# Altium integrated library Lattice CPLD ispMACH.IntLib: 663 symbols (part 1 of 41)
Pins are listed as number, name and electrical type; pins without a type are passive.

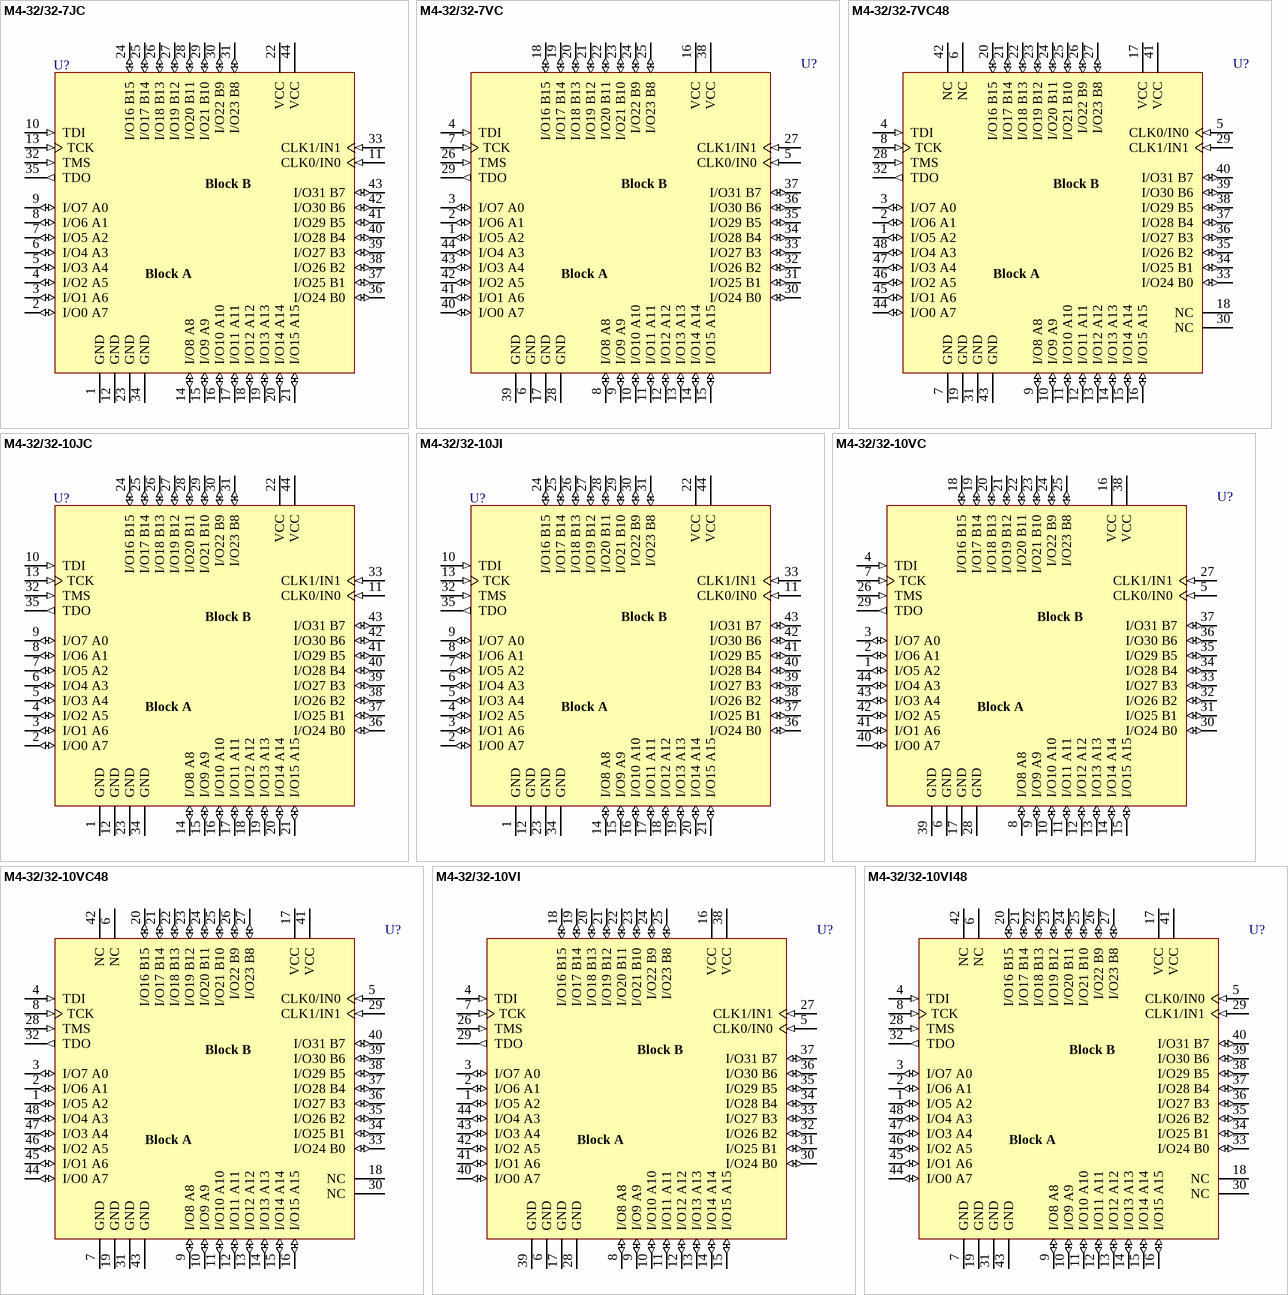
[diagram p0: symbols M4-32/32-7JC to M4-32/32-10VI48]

## M4-32/32-7JC
designator U?
High-Performance EE CMOS In-System Programmable Logic
footprint PLCC44_N (Leaded Chip Carrier, 44-Leads, Body 16.6x16.6mm, Pitch 1.27mm, IPC Medium Density)
footprint PLCC44_L (Leaded Chip Carrier, 44-Leads, Body 16.6x16.6mm, Pitch 1.27mm, IPC High Density)
footprint PLCC44_M (Leaded Chip Carrier, 44-Leads, Body 16.6x16.6mm, Pitch 1.27mm, IPC Low Density)
3D model M4-PLCC44 (44-Pin Leaded Chip Carrier 1.27 mm Pitch)
pins: 1 GND (power), 2 I/O0 A7 (io), 3 I/O1 A6 (io), 4 I/O2 A5 (io), 5 I/O3 A4 (io), 6 I/O4 A3 (io), 7 I/O5 A2 (io), 8 I/O6 A1 (io), 9 I/O7 A0 (io), 10 TDI (in), 11 CLK0/IN0 (in), 12 GND (power), 13 TCK (in), 14 I/O8 A8 (io), 15 I/O9 A9 (io), 16 I/O10 A10 (io), 17 I/O11 A11 (io), 18 I/O12 A12 (io), 19 I/O13 A13 (io), 20 I/O14 A14 (io), 21 I/O15 A15 (io), 22 VCC (power), 23 GND (power), 24 I/O16 B15 (io), 25 I/O17 B14 (io), 26 I/O18 B13 (io), 27 I/O19 B12 (io), 28 I/O20 B11 (io), 29 I/O21 B10 (io), 30 I/O22 B9 (io), 31 I/O23 B8 (io), 32 TMS (in), 33 CLK1/IN1 (in), 34 GND (power), 35 TDO (out), 36 I/O24 B0 (io), 37 I/O25 B1 (io), 38 I/O26 B2 (io), 39 I/O27 B3 (io), 40 I/O28 B4 (io), 41 I/O29 B5 (io), 42 I/O30 B6 (io), 43 I/O31 B7 (io), 44 VCC (power)

## M4-32/32-7VC
designator U?
High-Performance EE CMOS In-System Programmable Logic
footprint TQFP44_N (Thin QFP, 44-Leads, Body 10x10mm, Pitch 0.8mm, IPC Medium Density)
footprint TQFP44_L (Thin QFP, 44-Leads, Body 10x10mm, Pitch 0.8mm, IPC High Density)
footprint TQFP44_M (Thin QFP, 44-Leads, Body 10x10mm, Pitch 0.8mm, IPC Low Density)
3D model M4-TQFP44 (44-Pin Thin Quad Flat Pack 0.8 mm Pitch)
pins: 1 I/O5 A2 (io), 2 I/O6 A1 (io), 3 I/O7 A0 (io), 4 TDI (in), 5 CLK0/IN0 (in), 6 GND (power), 7 TCK (in), 8 I/O8 A8 (io), 9 I/O9 A9 (io), 10 I/O10 A10 (io), 11 I/O11 A11 (io), 12 I/O12 A12 (io), 13 I/O13 A13 (io), 14 I/O14 A14 (io), 15 I/O15 A15 (io), 16 VCC (power), 17 GND (power), 18 I/O16 B15 (io), 19 I/O17 B14 (io), 20 I/O18 B13 (io), 21 I/O19 B12 (io), 22 I/O20 B11 (io), 23 I/O21 B10 (io), 24 I/O22 B9 (io), 25 I/O23 B8 (io), 26 TMS (in), 27 CLK1/IN1 (in), 28 GND (power), 29 TDO (out), 30 I/O24 B0 (io), 31 I/O25 B1 (io), 32 I/O26 B2 (io), 33 I/O27 B3 (io), 34 I/O28 B4 (io), 35 I/O29 B5 (io), 36 I/O30 B6 (io), 37 I/O31 B7 (io), 38 VCC (power), 39 GND (power), 40 I/O0 A7 (io), 41 I/O1 A6 (io), 42 I/O2 A5 (io), 43 I/O3 A4 (io), 44 I/O4 A3 (io)

## M4-32/32-7VC48
designator U?
High-Performance EE CMOS In-System Programmable Logic
footprint TQFP48_N (Thin QFP, 48-Leads, Body 7x7mm, Pitch 0.5mm, IPC Medium Density)
footprint TQFP48_L (Thin QFP, 48-Leads, Body 7x7mm, Pitch 0.5mm, IPC High Density)
footprint TQFP48_M (Thin QFP, 48-Leads, Body 7x7mm, Pitch 0.5mm, IPC Low Density)
3D model M4-TQFP48 (48-Pin Thin Quad Flat Pack 0.5 mm Pitch)
pins: 1 I/O5 A2 (io), 2 I/O6 A1 (io), 3 I/O7 A0 (io), 4 TDI (in), 5 CLK0/IN0 (in), 6 NC, 7 GND (power), 8 TCK (in), 9 I/O8 A8 (io), 10 I/O9 A9 (io), 11 I/O10 A10 (io), 12 I/O11 A11 (io), 13 I/O12 A12 (io), 14 I/O13 A13 (io), 15 I/O14 A14 (io), 16 I/O15 A15 (io), 17 VCC (power), 18 NC, 19 GND (power), 20 I/O16 B15 (io), 21 I/O17 B14 (io), 22 I/O18 B13 (io), 23 I/O19 B12 (io), 24 I/O20 B11 (io), 25 I/O21 B10 (io), 26 I/O22 B9 (io), 27 I/O23 B8 (io), 28 TMS (in), 29 CLK1/IN1 (in), 30 NC, 31 GND (power), 32 TDO (out), 33 I/O24 B0 (io), 34 I/O25 B1 (io), 35 I/O26 B2 (io), 36 I/O27 B3 (io), 37 I/O28 B4 (io), 38 I/O29 B5 (io), 39 I/O30 B6 (io), 40 I/O31 B7 (io), 41 VCC (power), 42 NC, 43 GND (power), 44 I/O0 A7 (io), 45 I/O1 A6 (io), 46 I/O2 A5 (io), 47 I/O3 A4 (io), 48 I/O4 A3 (io)

## M4-32/32-10JC
designator U?
High-Performance EE CMOS In-System Programmable Logic
footprint PLCC44_N (Leaded Chip Carrier, 44-Leads, Body 16.6x16.6mm, Pitch 1.27mm, IPC Medium Density)
footprint PLCC44_L (Leaded Chip Carrier, 44-Leads, Body 16.6x16.6mm, Pitch 1.27mm, IPC High Density)
footprint PLCC44_M (Leaded Chip Carrier, 44-Leads, Body 16.6x16.6mm, Pitch 1.27mm, IPC Low Density)
3D model M4-PLCC44 (44-Pin Leaded Chip Carrier 1.27 mm Pitch)
pins: 1 GND (power), 2 I/O0 A7 (io), 3 I/O1 A6 (io), 4 I/O2 A5 (io), 5 I/O3 A4 (io), 6 I/O4 A3 (io), 7 I/O5 A2 (io), 8 I/O6 A1 (io), 9 I/O7 A0 (io), 10 TDI (in), 11 CLK0/IN0 (in), 12 GND (power), 13 TCK (in), 14 I/O8 A8 (io), 15 I/O9 A9 (io), 16 I/O10 A10 (io), 17 I/O11 A11 (io), 18 I/O12 A12 (io), 19 I/O13 A13 (io), 20 I/O14 A14 (io), 21 I/O15 A15 (io), 22 VCC (power), 23 GND (power), 24 I/O16 B15 (io), 25 I/O17 B14 (io), 26 I/O18 B13 (io), 27 I/O19 B12 (io), 28 I/O20 B11 (io), 29 I/O21 B10 (io), 30 I/O22 B9 (io), 31 I/O23 B8 (io), 32 TMS (in), 33 CLK1/IN1 (in), 34 GND (power), 35 TDO (out), 36 I/O24 B0 (io), 37 I/O25 B1 (io), 38 I/O26 B2 (io), 39 I/O27 B3 (io), 40 I/O28 B4 (io), 41 I/O29 B5 (io), 42 I/O30 B6 (io), 43 I/O31 B7 (io), 44 VCC (power)

## M4-32/32-10JI
designator U?
High-Performance EE CMOS In-System Programmable Logic
footprint PLCC44_N (Leaded Chip Carrier, 44-Leads, Body 16.6x16.6mm, Pitch 1.27mm, IPC Medium Density)
footprint PLCC44_L (Leaded Chip Carrier, 44-Leads, Body 16.6x16.6mm, Pitch 1.27mm, IPC High Density)
footprint PLCC44_M (Leaded Chip Carrier, 44-Leads, Body 16.6x16.6mm, Pitch 1.27mm, IPC Low Density)
3D model M4-PLCC44 (44-Pin Leaded Chip Carrier 1.27 mm Pitch)
pins: 1 GND (power), 2 I/O0 A7 (io), 3 I/O1 A6 (io), 4 I/O2 A5 (io), 5 I/O3 A4 (io), 6 I/O4 A3 (io), 7 I/O5 A2 (io), 8 I/O6 A1 (io), 9 I/O7 A0 (io), 10 TDI (in), 11 CLK0/IN0 (in), 12 GND (power), 13 TCK (in), 14 I/O8 A8 (io), 15 I/O9 A9 (io), 16 I/O10 A10 (io), 17 I/O11 A11 (io), 18 I/O12 A12 (io), 19 I/O13 A13 (io), 20 I/O14 A14 (io), 21 I/O15 A15 (io), 22 VCC (power), 23 GND (power), 24 I/O16 B15 (io), 25 I/O17 B14 (io), 26 I/O18 B13 (io), 27 I/O19 B12 (io), 28 I/O20 B11 (io), 29 I/O21 B10 (io), 30 I/O22 B9 (io), 31 I/O23 B8 (io), 32 TMS (in), 33 CLK1/IN1 (in), 34 GND (power), 35 TDO (out), 36 I/O24 B0 (io), 37 I/O25 B1 (io), 38 I/O26 B2 (io), 39 I/O27 B3 (io), 40 I/O28 B4 (io), 41 I/O29 B5 (io), 42 I/O30 B6 (io), 43 I/O31 B7 (io), 44 VCC (power)

## M4-32/32-10VC
designator U?
High-Performance EE CMOS In-System Programmable Logic
footprint TQFP44_N (Thin QFP, 44-Leads, Body 10x10mm, Pitch 0.8mm, IPC Medium Density)
footprint TQFP44_L (Thin QFP, 44-Leads, Body 10x10mm, Pitch 0.8mm, IPC High Density)
footprint TQFP44_M (Thin QFP, 44-Leads, Body 10x10mm, Pitch 0.8mm, IPC Low Density)
3D model M4-TQFP44 (44-Pin Thin Quad Flat Pack 0.8 mm Pitch)
pins: 1 I/O5 A2 (io), 2 I/O6 A1 (io), 3 I/O7 A0 (io), 4 TDI (in), 5 CLK0/IN0 (in), 6 GND (power), 7 TCK (in), 8 I/O8 A8 (io), 9 I/O9 A9 (io), 10 I/O10 A10 (io), 11 I/O11 A11 (io), 12 I/O12 A12 (io), 13 I/O13 A13 (io), 14 I/O14 A14 (io), 15 I/O15 A15 (io), 16 VCC (power), 17 GND (power), 18 I/O16 B15 (io), 19 I/O17 B14 (io), 20 I/O18 B13 (io), 21 I/O19 B12 (io), 22 I/O20 B11 (io), 23 I/O21 B10 (io), 24 I/O22 B9 (io), 25 I/O23 B8 (io), 26 TMS (in), 27 CLK1/IN1 (in), 28 GND (power), 29 TDO (out), 30 I/O24 B0 (io), 31 I/O25 B1 (io), 32 I/O26 B2 (io), 33 I/O27 B3 (io), 34 I/O28 B4 (io), 35 I/O29 B5 (io), 36 I/O30 B6 (io), 37 I/O31 B7 (io), 38 VCC (power), 39 GND (power), 40 I/O0 A7 (io), 41 I/O1 A6 (io), 42 I/O2 A5 (io), 43 I/O3 A4 (io), 44 I/O4 A3 (io)

## M4-32/32-10VC48
designator U?
High-Performance EE CMOS In-System Programmable Logic
footprint TQFP48_N (Thin QFP, 48-Leads, Body 7x7mm, Pitch 0.5mm, IPC Medium Density)
footprint TQFP48_L (Thin QFP, 48-Leads, Body 7x7mm, Pitch 0.5mm, IPC High Density)
footprint TQFP48_M (Thin QFP, 48-Leads, Body 7x7mm, Pitch 0.5mm, IPC Low Density)
3D model M4-TQFP48 (48-Pin Thin Quad Flat Pack 0.5 mm Pitch)
pins: 1 I/O5 A2 (io), 2 I/O6 A1 (io), 3 I/O7 A0 (io), 4 TDI (in), 5 CLK0/IN0 (in), 6 NC, 7 GND (power), 8 TCK (in), 9 I/O8 A8 (io), 10 I/O9 A9 (io), 11 I/O10 A10 (io), 12 I/O11 A11 (io), 13 I/O12 A12 (io), 14 I/O13 A13 (io), 15 I/O14 A14 (io), 16 I/O15 A15 (io), 17 VCC (power), 18 NC, 19 GND (power), 20 I/O16 B15 (io), 21 I/O17 B14 (io), 22 I/O18 B13 (io), 23 I/O19 B12 (io), 24 I/O20 B11 (io), 25 I/O21 B10 (io), 26 I/O22 B9 (io), 27 I/O23 B8 (io), 28 TMS (in), 29 CLK1/IN1 (in), 30 NC, 31 GND (power), 32 TDO (out), 33 I/O24 B0 (io), 34 I/O25 B1 (io), 35 I/O26 B2 (io), 36 I/O27 B3 (io), 37 I/O28 B4 (io), 38 I/O29 B5 (io), 39 I/O30 B6 (io), 40 I/O31 B7 (io), 41 VCC (power), 42 NC, 43 GND (power), 44 I/O0 A7 (io), 45 I/O1 A6 (io), 46 I/O2 A5 (io), 47 I/O3 A4 (io), 48 I/O4 A3 (io)

## M4-32/32-10VI
designator U?
High-Performance EE CMOS In-System Programmable Logic
footprint TQFP44_N (Thin QFP, 44-Leads, Body 10x10mm, Pitch 0.8mm, IPC Medium Density)
footprint TQFP44_L (Thin QFP, 44-Leads, Body 10x10mm, Pitch 0.8mm, IPC High Density)
footprint TQFP44_M (Thin QFP, 44-Leads, Body 10x10mm, Pitch 0.8mm, IPC Low Density)
3D model M4-TQFP44 (44-Pin Thin Quad Flat Pack 0.8 mm Pitch)
pins: 1 I/O5 A2 (io), 2 I/O6 A1 (io), 3 I/O7 A0 (io), 4 TDI (in), 5 CLK0/IN0 (in), 6 GND (power), 7 TCK (in), 8 I/O8 A8 (io), 9 I/O9 A9 (io), 10 I/O10 A10 (io), 11 I/O11 A11 (io), 12 I/O12 A12 (io), 13 I/O13 A13 (io), 14 I/O14 A14 (io), 15 I/O15 A15 (io), 16 VCC (power), 17 GND (power), 18 I/O16 B15 (io), 19 I/O17 B14 (io), 20 I/O18 B13 (io), 21 I/O19 B12 (io), 22 I/O20 B11 (io), 23 I/O21 B10 (io), 24 I/O22 B9 (io), 25 I/O23 B8 (io), 26 TMS (in), 27 CLK1/IN1 (in), 28 GND (power), 29 TDO (out), 30 I/O24 B0 (io), 31 I/O25 B1 (io), 32 I/O26 B2 (io), 33 I/O27 B3 (io), 34 I/O28 B4 (io), 35 I/O29 B5 (io), 36 I/O30 B6 (io), 37 I/O31 B7 (io), 38 VCC (power), 39 GND (power), 40 I/O0 A7 (io), 41 I/O1 A6 (io), 42 I/O2 A5 (io), 43 I/O3 A4 (io), 44 I/O4 A3 (io)

## M4-32/32-10VI48
designator U?
High-Performance EE CMOS In-System Programmable Logic
footprint TQFP48_N (Thin QFP, 48-Leads, Body 7x7mm, Pitch 0.5mm, IPC Medium Density)
footprint TQFP48_L (Thin QFP, 48-Leads, Body 7x7mm, Pitch 0.5mm, IPC High Density)
footprint TQFP48_M (Thin QFP, 48-Leads, Body 7x7mm, Pitch 0.5mm, IPC Low Density)
3D model M4-TQFP48 (48-Pin Thin Quad Flat Pack 0.5 mm Pitch)
pins: 1 I/O5 A2 (io), 2 I/O6 A1 (io), 3 I/O7 A0 (io), 4 TDI (in), 5 CLK0/IN0 (in), 6 NC, 7 GND (power), 8 TCK (in), 9 I/O8 A8 (io), 10 I/O9 A9 (io), 11 I/O10 A10 (io), 12 I/O11 A11 (io), 13 I/O12 A12 (io), 14 I/O13 A13 (io), 15 I/O14 A14 (io), 16 I/O15 A15 (io), 17 VCC (power), 18 NC, 19 GND (power), 20 I/O16 B15 (io), 21 I/O17 B14 (io), 22 I/O18 B13 (io), 23 I/O19 B12 (io), 24 I/O20 B11 (io), 25 I/O21 B10 (io), 26 I/O22 B9 (io), 27 I/O23 B8 (io), 28 TMS (in), 29 CLK1/IN1 (in), 30 NC, 31 GND (power), 32 TDO (out), 33 I/O24 B0 (io), 34 I/O25 B1 (io), 35 I/O26 B2 (io), 36 I/O27 B3 (io), 37 I/O28 B4 (io), 38 I/O29 B5 (io), 39 I/O30 B6 (io), 40 I/O31 B7 (io), 41 VCC (power), 42 NC, 43 GND (power), 44 I/O0 A7 (io), 45 I/O1 A6 (io), 46 I/O2 A5 (io), 47 I/O3 A4 (io), 48 I/O4 A3 (io)

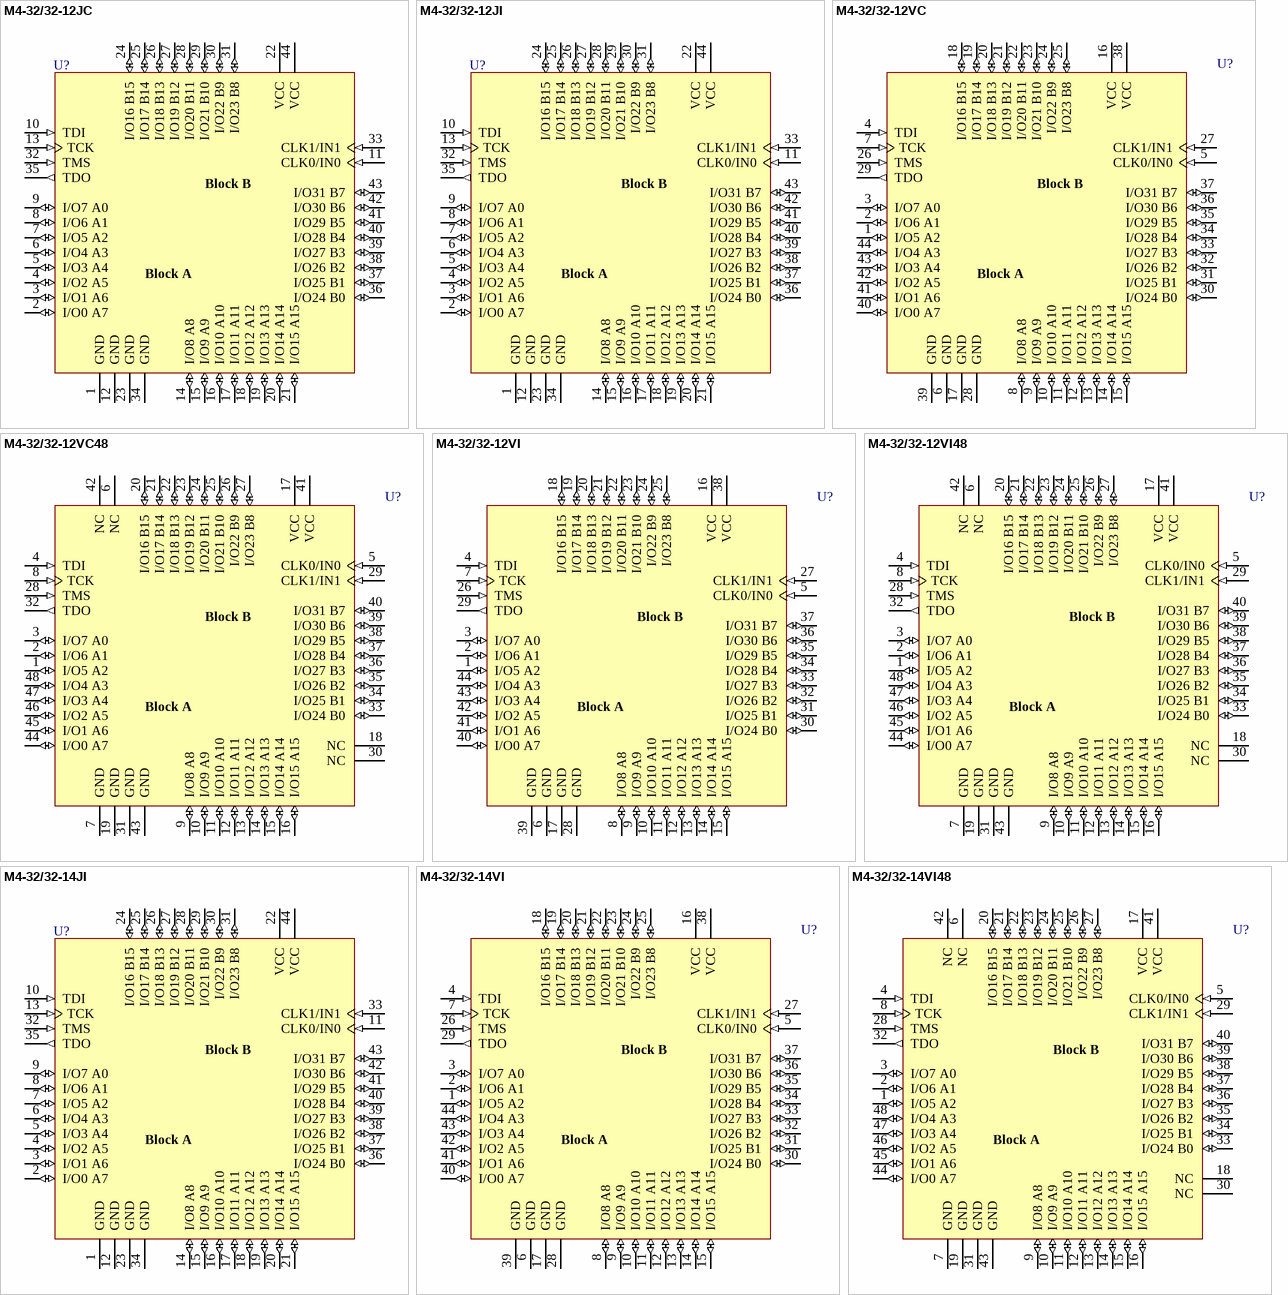
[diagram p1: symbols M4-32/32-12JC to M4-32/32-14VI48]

## M4-32/32-12JC
designator U?
High-Performance EE CMOS In-System Programmable Logic
footprint PLCC44_N (Leaded Chip Carrier, 44-Leads, Body 16.6x16.6mm, Pitch 1.27mm, IPC Medium Density)
footprint PLCC44_L (Leaded Chip Carrier, 44-Leads, Body 16.6x16.6mm, Pitch 1.27mm, IPC High Density)
footprint PLCC44_M (Leaded Chip Carrier, 44-Leads, Body 16.6x16.6mm, Pitch 1.27mm, IPC Low Density)
3D model M4-PLCC44 (44-Pin Leaded Chip Carrier 1.27 mm Pitch)
pins: 1 GND (power), 2 I/O0 A7 (io), 3 I/O1 A6 (io), 4 I/O2 A5 (io), 5 I/O3 A4 (io), 6 I/O4 A3 (io), 7 I/O5 A2 (io), 8 I/O6 A1 (io), 9 I/O7 A0 (io), 10 TDI (in), 11 CLK0/IN0 (in), 12 GND (power), 13 TCK (in), 14 I/O8 A8 (io), 15 I/O9 A9 (io), 16 I/O10 A10 (io), 17 I/O11 A11 (io), 18 I/O12 A12 (io), 19 I/O13 A13 (io), 20 I/O14 A14 (io), 21 I/O15 A15 (io), 22 VCC (power), 23 GND (power), 24 I/O16 B15 (io), 25 I/O17 B14 (io), 26 I/O18 B13 (io), 27 I/O19 B12 (io), 28 I/O20 B11 (io), 29 I/O21 B10 (io), 30 I/O22 B9 (io), 31 I/O23 B8 (io), 32 TMS (in), 33 CLK1/IN1 (in), 34 GND (power), 35 TDO (out), 36 I/O24 B0 (io), 37 I/O25 B1 (io), 38 I/O26 B2 (io), 39 I/O27 B3 (io), 40 I/O28 B4 (io), 41 I/O29 B5 (io), 42 I/O30 B6 (io), 43 I/O31 B7 (io), 44 VCC (power)

## M4-32/32-12JI
designator U?
High-Performance EE CMOS In-System Programmable Logic
footprint PLCC44_N (Leaded Chip Carrier, 44-Leads, Body 16.6x16.6mm, Pitch 1.27mm, IPC Medium Density)
footprint PLCC44_L (Leaded Chip Carrier, 44-Leads, Body 16.6x16.6mm, Pitch 1.27mm, IPC High Density)
footprint PLCC44_M (Leaded Chip Carrier, 44-Leads, Body 16.6x16.6mm, Pitch 1.27mm, IPC Low Density)
3D model M4-PLCC44 (44-Pin Leaded Chip Carrier 1.27 mm Pitch)
pins: 1 GND (power), 2 I/O0 A7 (io), 3 I/O1 A6 (io), 4 I/O2 A5 (io), 5 I/O3 A4 (io), 6 I/O4 A3 (io), 7 I/O5 A2 (io), 8 I/O6 A1 (io), 9 I/O7 A0 (io), 10 TDI (in), 11 CLK0/IN0 (in), 12 GND (power), 13 TCK (in), 14 I/O8 A8 (io), 15 I/O9 A9 (io), 16 I/O10 A10 (io), 17 I/O11 A11 (io), 18 I/O12 A12 (io), 19 I/O13 A13 (io), 20 I/O14 A14 (io), 21 I/O15 A15 (io), 22 VCC (power), 23 GND (power), 24 I/O16 B15 (io), 25 I/O17 B14 (io), 26 I/O18 B13 (io), 27 I/O19 B12 (io), 28 I/O20 B11 (io), 29 I/O21 B10 (io), 30 I/O22 B9 (io), 31 I/O23 B8 (io), 32 TMS (in), 33 CLK1/IN1 (in), 34 GND (power), 35 TDO (out), 36 I/O24 B0 (io), 37 I/O25 B1 (io), 38 I/O26 B2 (io), 39 I/O27 B3 (io), 40 I/O28 B4 (io), 41 I/O29 B5 (io), 42 I/O30 B6 (io), 43 I/O31 B7 (io), 44 VCC (power)

## M4-32/32-12VC
designator U?
High-Performance EE CMOS In-System Programmable Logic
footprint TQFP44_N (Thin QFP, 44-Leads, Body 10x10mm, Pitch 0.8mm, IPC Medium Density)
footprint TQFP44_L (Thin QFP, 44-Leads, Body 10x10mm, Pitch 0.8mm, IPC High Density)
footprint TQFP44_M (Thin QFP, 44-Leads, Body 10x10mm, Pitch 0.8mm, IPC Low Density)
3D model M4-TQFP44 (44-Pin Thin Quad Flat Pack 0.8 mm Pitch)
pins: 1 I/O5 A2 (io), 2 I/O6 A1 (io), 3 I/O7 A0 (io), 4 TDI (in), 5 CLK0/IN0 (in), 6 GND (power), 7 TCK (in), 8 I/O8 A8 (io), 9 I/O9 A9 (io), 10 I/O10 A10 (io), 11 I/O11 A11 (io), 12 I/O12 A12 (io), 13 I/O13 A13 (io), 14 I/O14 A14 (io), 15 I/O15 A15 (io), 16 VCC (power), 17 GND (power), 18 I/O16 B15 (io), 19 I/O17 B14 (io), 20 I/O18 B13 (io), 21 I/O19 B12 (io), 22 I/O20 B11 (io), 23 I/O21 B10 (io), 24 I/O22 B9 (io), 25 I/O23 B8 (io), 26 TMS (in), 27 CLK1/IN1 (in), 28 GND (power), 29 TDO (out), 30 I/O24 B0 (io), 31 I/O25 B1 (io), 32 I/O26 B2 (io), 33 I/O27 B3 (io), 34 I/O28 B4 (io), 35 I/O29 B5 (io), 36 I/O30 B6 (io), 37 I/O31 B7 (io), 38 VCC (power), 39 GND (power), 40 I/O0 A7 (io), 41 I/O1 A6 (io), 42 I/O2 A5 (io), 43 I/O3 A4 (io), 44 I/O4 A3 (io)

## M4-32/32-12VC48
designator U?
High-Performance EE CMOS In-System Programmable Logic
footprint TQFP48_N (Thin QFP, 48-Leads, Body 7x7mm, Pitch 0.5mm, IPC Medium Density)
footprint TQFP48_L (Thin QFP, 48-Leads, Body 7x7mm, Pitch 0.5mm, IPC High Density)
footprint TQFP48_M (Thin QFP, 48-Leads, Body 7x7mm, Pitch 0.5mm, IPC Low Density)
3D model M4-TQFP48 (48-Pin Thin Quad Flat Pack 0.5 mm Pitch)
pins: 1 I/O5 A2 (io), 2 I/O6 A1 (io), 3 I/O7 A0 (io), 4 TDI (in), 5 CLK0/IN0 (in), 6 NC, 7 GND (power), 8 TCK (in), 9 I/O8 A8 (io), 10 I/O9 A9 (io), 11 I/O10 A10 (io), 12 I/O11 A11 (io), 13 I/O12 A12 (io), 14 I/O13 A13 (io), 15 I/O14 A14 (io), 16 I/O15 A15 (io), 17 VCC (power), 18 NC, 19 GND (power), 20 I/O16 B15 (io), 21 I/O17 B14 (io), 22 I/O18 B13 (io), 23 I/O19 B12 (io), 24 I/O20 B11 (io), 25 I/O21 B10 (io), 26 I/O22 B9 (io), 27 I/O23 B8 (io), 28 TMS (in), 29 CLK1/IN1 (in), 30 NC, 31 GND (power), 32 TDO (out), 33 I/O24 B0 (io), 34 I/O25 B1 (io), 35 I/O26 B2 (io), 36 I/O27 B3 (io), 37 I/O28 B4 (io), 38 I/O29 B5 (io), 39 I/O30 B6 (io), 40 I/O31 B7 (io), 41 VCC (power), 42 NC, 43 GND (power), 44 I/O0 A7 (io), 45 I/O1 A6 (io), 46 I/O2 A5 (io), 47 I/O3 A4 (io), 48 I/O4 A3 (io)

## M4-32/32-12VI
designator U?
High-Performance EE CMOS In-System Programmable Logic
footprint TQFP44_N (Thin QFP, 44-Leads, Body 10x10mm, Pitch 0.8mm, IPC Medium Density)
footprint TQFP44_L (Thin QFP, 44-Leads, Body 10x10mm, Pitch 0.8mm, IPC High Density)
footprint TQFP44_M (Thin QFP, 44-Leads, Body 10x10mm, Pitch 0.8mm, IPC Low Density)
3D model M4-TQFP44 (44-Pin Thin Quad Flat Pack 0.8 mm Pitch)
pins: 1 I/O5 A2 (io), 2 I/O6 A1 (io), 3 I/O7 A0 (io), 4 TDI (in), 5 CLK0/IN0 (in), 6 GND (power), 7 TCK (in), 8 I/O8 A8 (io), 9 I/O9 A9 (io), 10 I/O10 A10 (io), 11 I/O11 A11 (io), 12 I/O12 A12 (io), 13 I/O13 A13 (io), 14 I/O14 A14 (io), 15 I/O15 A15 (io), 16 VCC (power), 17 GND (power), 18 I/O16 B15 (io), 19 I/O17 B14 (io), 20 I/O18 B13 (io), 21 I/O19 B12 (io), 22 I/O20 B11 (io), 23 I/O21 B10 (io), 24 I/O22 B9 (io), 25 I/O23 B8 (io), 26 TMS (in), 27 CLK1/IN1 (in), 28 GND (power), 29 TDO (out), 30 I/O24 B0 (io), 31 I/O25 B1 (io), 32 I/O26 B2 (io), 33 I/O27 B3 (io), 34 I/O28 B4 (io), 35 I/O29 B5 (io), 36 I/O30 B6 (io), 37 I/O31 B7 (io), 38 VCC (power), 39 GND (power), 40 I/O0 A7 (io), 41 I/O1 A6 (io), 42 I/O2 A5 (io), 43 I/O3 A4 (io), 44 I/O4 A3 (io)

## M4-32/32-12VI48
designator U?
High-Performance EE CMOS In-System Programmable Logic
footprint TQFP48_N (Thin QFP, 48-Leads, Body 7x7mm, Pitch 0.5mm, IPC Medium Density)
footprint TQFP48_L (Thin QFP, 48-Leads, Body 7x7mm, Pitch 0.5mm, IPC High Density)
footprint TQFP48_M (Thin QFP, 48-Leads, Body 7x7mm, Pitch 0.5mm, IPC Low Density)
3D model M4-TQFP48 (48-Pin Thin Quad Flat Pack 0.5 mm Pitch)
pins: 1 I/O5 A2 (io), 2 I/O6 A1 (io), 3 I/O7 A0 (io), 4 TDI (in), 5 CLK0/IN0 (in), 6 NC, 7 GND (power), 8 TCK (in), 9 I/O8 A8 (io), 10 I/O9 A9 (io), 11 I/O10 A10 (io), 12 I/O11 A11 (io), 13 I/O12 A12 (io), 14 I/O13 A13 (io), 15 I/O14 A14 (io), 16 I/O15 A15 (io), 17 VCC (power), 18 NC, 19 GND (power), 20 I/O16 B15 (io), 21 I/O17 B14 (io), 22 I/O18 B13 (io), 23 I/O19 B12 (io), 24 I/O20 B11 (io), 25 I/O21 B10 (io), 26 I/O22 B9 (io), 27 I/O23 B8 (io), 28 TMS (in), 29 CLK1/IN1 (in), 30 NC, 31 GND (power), 32 TDO (out), 33 I/O24 B0 (io), 34 I/O25 B1 (io), 35 I/O26 B2 (io), 36 I/O27 B3 (io), 37 I/O28 B4 (io), 38 I/O29 B5 (io), 39 I/O30 B6 (io), 40 I/O31 B7 (io), 41 VCC (power), 42 NC, 43 GND (power), 44 I/O0 A7 (io), 45 I/O1 A6 (io), 46 I/O2 A5 (io), 47 I/O3 A4 (io), 48 I/O4 A3 (io)

## M4-32/32-14JI
designator U?
High-Performance EE CMOS In-System Programmable Logic
footprint PLCC44_N (Leaded Chip Carrier, 44-Leads, Body 16.6x16.6mm, Pitch 1.27mm, IPC Medium Density)
footprint PLCC44_L (Leaded Chip Carrier, 44-Leads, Body 16.6x16.6mm, Pitch 1.27mm, IPC High Density)
footprint PLCC44_M (Leaded Chip Carrier, 44-Leads, Body 16.6x16.6mm, Pitch 1.27mm, IPC Low Density)
3D model M4-PLCC44 (44-Pin Leaded Chip Carrier 1.27 mm Pitch)
pins: 1 GND (power), 2 I/O0 A7 (io), 3 I/O1 A6 (io), 4 I/O2 A5 (io), 5 I/O3 A4 (io), 6 I/O4 A3 (io), 7 I/O5 A2 (io), 8 I/O6 A1 (io), 9 I/O7 A0 (io), 10 TDI (in), 11 CLK0/IN0 (in), 12 GND (power), 13 TCK (in), 14 I/O8 A8 (io), 15 I/O9 A9 (io), 16 I/O10 A10 (io), 17 I/O11 A11 (io), 18 I/O12 A12 (io), 19 I/O13 A13 (io), 20 I/O14 A14 (io), 21 I/O15 A15 (io), 22 VCC (power), 23 GND (power), 24 I/O16 B15 (io), 25 I/O17 B14 (io), 26 I/O18 B13 (io), 27 I/O19 B12 (io), 28 I/O20 B11 (io), 29 I/O21 B10 (io), 30 I/O22 B9 (io), 31 I/O23 B8 (io), 32 TMS (in), 33 CLK1/IN1 (in), 34 GND (power), 35 TDO (out), 36 I/O24 B0 (io), 37 I/O25 B1 (io), 38 I/O26 B2 (io), 39 I/O27 B3 (io), 40 I/O28 B4 (io), 41 I/O29 B5 (io), 42 I/O30 B6 (io), 43 I/O31 B7 (io), 44 VCC (power)

## M4-32/32-14VI
designator U?
High-Performance EE CMOS In-System Programmable Logic
footprint TQFP44_N (Thin QFP, 44-Leads, Body 10x10mm, Pitch 0.8mm, IPC Medium Density)
footprint TQFP44_L (Thin QFP, 44-Leads, Body 10x10mm, Pitch 0.8mm, IPC High Density)
footprint TQFP44_M (Thin QFP, 44-Leads, Body 10x10mm, Pitch 0.8mm, IPC Low Density)
3D model M4-TQFP44 (44-Pin Thin Quad Flat Pack 0.8 mm Pitch)
pins: 1 I/O5 A2 (io), 2 I/O6 A1 (io), 3 I/O7 A0 (io), 4 TDI (in), 5 CLK0/IN0 (in), 6 GND (power), 7 TCK (in), 8 I/O8 A8 (io), 9 I/O9 A9 (io), 10 I/O10 A10 (io), 11 I/O11 A11 (io), 12 I/O12 A12 (io), 13 I/O13 A13 (io), 14 I/O14 A14 (io), 15 I/O15 A15 (io), 16 VCC (power), 17 GND (power), 18 I/O16 B15 (io), 19 I/O17 B14 (io), 20 I/O18 B13 (io), 21 I/O19 B12 (io), 22 I/O20 B11 (io), 23 I/O21 B10 (io), 24 I/O22 B9 (io), 25 I/O23 B8 (io), 26 TMS (in), 27 CLK1/IN1 (in), 28 GND (power), 29 TDO (out), 30 I/O24 B0 (io), 31 I/O25 B1 (io), 32 I/O26 B2 (io), 33 I/O27 B3 (io), 34 I/O28 B4 (io), 35 I/O29 B5 (io), 36 I/O30 B6 (io), 37 I/O31 B7 (io), 38 VCC (power), 39 GND (power), 40 I/O0 A7 (io), 41 I/O1 A6 (io), 42 I/O2 A5 (io), 43 I/O3 A4 (io), 44 I/O4 A3 (io)

## M4-32/32-14VI48
designator U?
High-Performance EE CMOS In-System Programmable Logic
footprint TQFP48_N (Thin QFP, 48-Leads, Body 7x7mm, Pitch 0.5mm, IPC Medium Density)
footprint TQFP48_L (Thin QFP, 48-Leads, Body 7x7mm, Pitch 0.5mm, IPC High Density)
footprint TQFP48_M (Thin QFP, 48-Leads, Body 7x7mm, Pitch 0.5mm, IPC Low Density)
3D model M4-TQFP48 (48-Pin Thin Quad Flat Pack 0.5 mm Pitch)
pins: 1 I/O5 A2 (io), 2 I/O6 A1 (io), 3 I/O7 A0 (io), 4 TDI (in), 5 CLK0/IN0 (in), 6 NC, 7 GND (power), 8 TCK (in), 9 I/O8 A8 (io), 10 I/O9 A9 (io), 11 I/O10 A10 (io), 12 I/O11 A11 (io), 13 I/O12 A12 (io), 14 I/O13 A13 (io), 15 I/O14 A14 (io), 16 I/O15 A15 (io), 17 VCC (power), 18 NC, 19 GND (power), 20 I/O16 B15 (io), 21 I/O17 B14 (io), 22 I/O18 B13 (io), 23 I/O19 B12 (io), 24 I/O20 B11 (io), 25 I/O21 B10 (io), 26 I/O22 B9 (io), 27 I/O23 B8 (io), 28 TMS (in), 29 CLK1/IN1 (in), 30 NC, 31 GND (power), 32 TDO (out), 33 I/O24 B0 (io), 34 I/O25 B1 (io), 35 I/O26 B2 (io), 36 I/O27 B3 (io), 37 I/O28 B4 (io), 38 I/O29 B5 (io), 39 I/O30 B6 (io), 40 I/O31 B7 (io), 41 VCC (power), 42 NC, 43 GND (power), 44 I/O0 A7 (io), 45 I/O1 A6 (io), 46 I/O2 A5 (io), 47 I/O3 A4 (io), 48 I/O4 A3 (io)

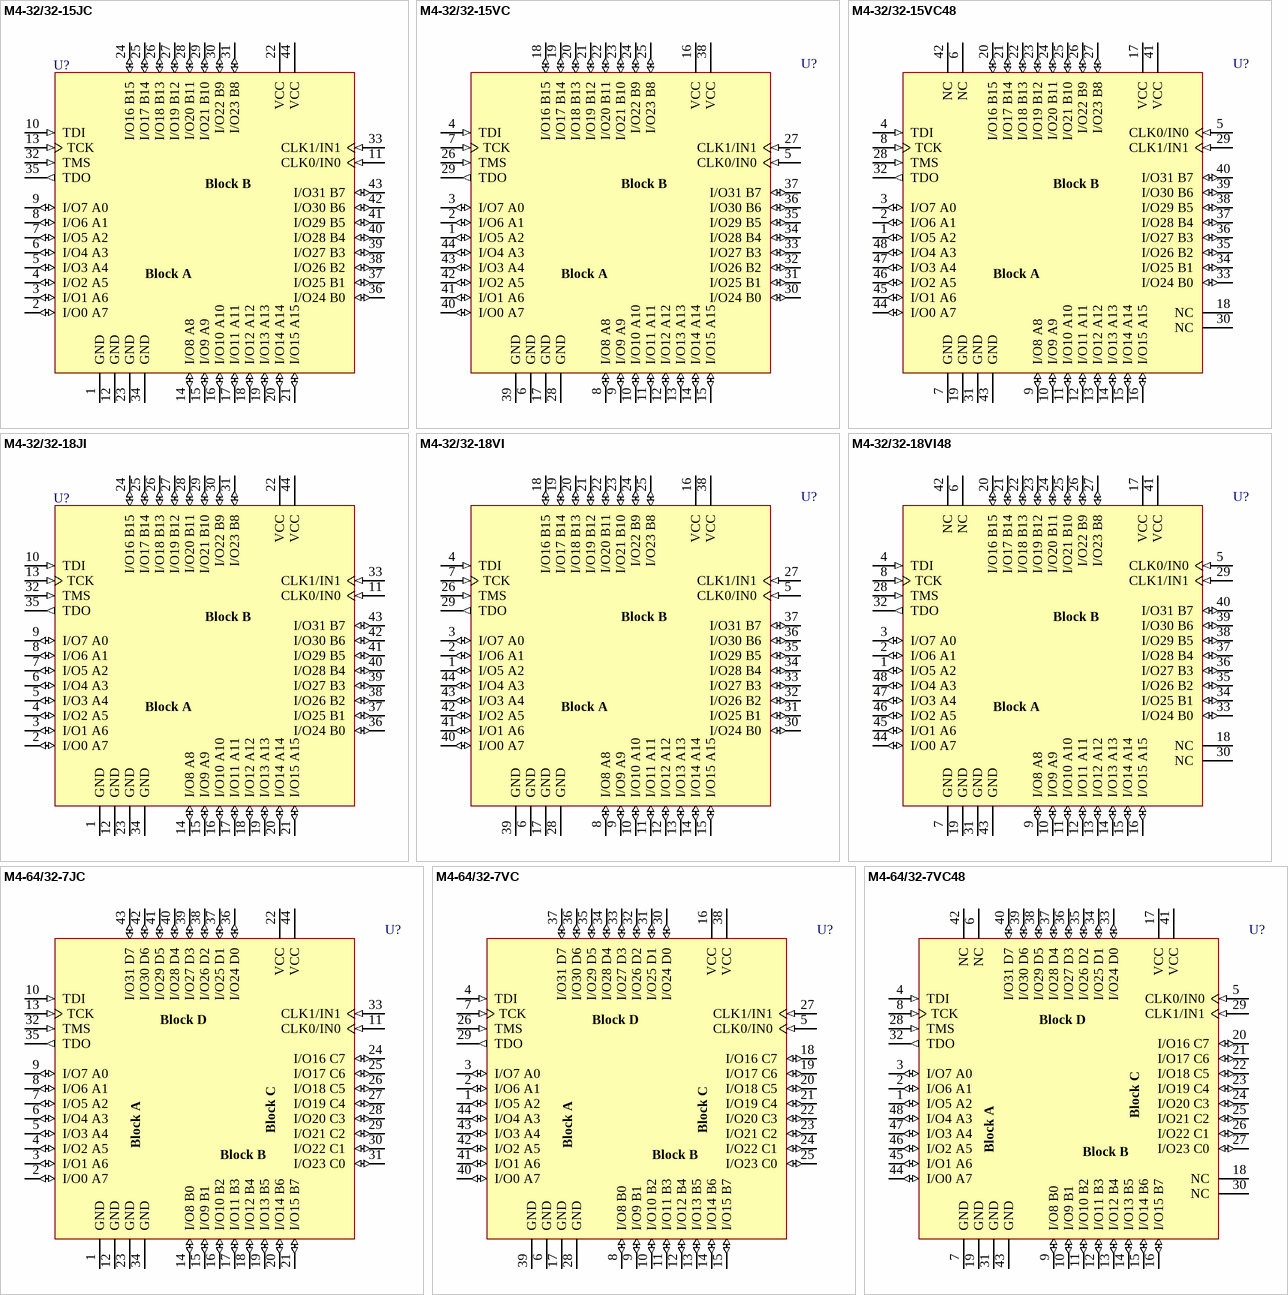
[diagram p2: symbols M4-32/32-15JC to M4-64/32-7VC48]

## M4-32/32-15JC
designator U?
High-Performance EE CMOS In-System Programmable Logic
footprint PLCC44_N (Leaded Chip Carrier, 44-Leads, Body 16.6x16.6mm, Pitch 1.27mm, IPC Medium Density)
footprint PLCC44_L (Leaded Chip Carrier, 44-Leads, Body 16.6x16.6mm, Pitch 1.27mm, IPC High Density)
footprint PLCC44_M (Leaded Chip Carrier, 44-Leads, Body 16.6x16.6mm, Pitch 1.27mm, IPC Low Density)
3D model M4-PLCC44 (44-Pin Leaded Chip Carrier 1.27 mm Pitch)
pins: 1 GND (power), 2 I/O0 A7 (io), 3 I/O1 A6 (io), 4 I/O2 A5 (io), 5 I/O3 A4 (io), 6 I/O4 A3 (io), 7 I/O5 A2 (io), 8 I/O6 A1 (io), 9 I/O7 A0 (io), 10 TDI (in), 11 CLK0/IN0 (in), 12 GND (power), 13 TCK (in), 14 I/O8 A8 (io), 15 I/O9 A9 (io), 16 I/O10 A10 (io), 17 I/O11 A11 (io), 18 I/O12 A12 (io), 19 I/O13 A13 (io), 20 I/O14 A14 (io), 21 I/O15 A15 (io), 22 VCC (power), 23 GND (power), 24 I/O16 B15 (io), 25 I/O17 B14 (io), 26 I/O18 B13 (io), 27 I/O19 B12 (io), 28 I/O20 B11 (io), 29 I/O21 B10 (io), 30 I/O22 B9 (io), 31 I/O23 B8 (io), 32 TMS (in), 33 CLK1/IN1 (in), 34 GND (power), 35 TDO (out), 36 I/O24 B0 (io), 37 I/O25 B1 (io), 38 I/O26 B2 (io), 39 I/O27 B3 (io), 40 I/O28 B4 (io), 41 I/O29 B5 (io), 42 I/O30 B6 (io), 43 I/O31 B7 (io), 44 VCC (power)

## M4-32/32-15VC
designator U?
High-Performance EE CMOS In-System Programmable Logic
footprint TQFP44_N (Thin QFP, 44-Leads, Body 10x10mm, Pitch 0.8mm, IPC Medium Density)
footprint TQFP44_L (Thin QFP, 44-Leads, Body 10x10mm, Pitch 0.8mm, IPC High Density)
footprint TQFP44_M (Thin QFP, 44-Leads, Body 10x10mm, Pitch 0.8mm, IPC Low Density)
3D model M4-TQFP44 (44-Pin Thin Quad Flat Pack 0.8 mm Pitch)
pins: 1 I/O5 A2 (io), 2 I/O6 A1 (io), 3 I/O7 A0 (io), 4 TDI (in), 5 CLK0/IN0 (in), 6 GND (power), 7 TCK (in), 8 I/O8 A8 (io), 9 I/O9 A9 (io), 10 I/O10 A10 (io), 11 I/O11 A11 (io), 12 I/O12 A12 (io), 13 I/O13 A13 (io), 14 I/O14 A14 (io), 15 I/O15 A15 (io), 16 VCC (power), 17 GND (power), 18 I/O16 B15 (io), 19 I/O17 B14 (io), 20 I/O18 B13 (io), 21 I/O19 B12 (io), 22 I/O20 B11 (io), 23 I/O21 B10 (io), 24 I/O22 B9 (io), 25 I/O23 B8 (io), 26 TMS (in), 27 CLK1/IN1 (in), 28 GND (power), 29 TDO (out), 30 I/O24 B0 (io), 31 I/O25 B1 (io), 32 I/O26 B2 (io), 33 I/O27 B3 (io), 34 I/O28 B4 (io), 35 I/O29 B5 (io), 36 I/O30 B6 (io), 37 I/O31 B7 (io), 38 VCC (power), 39 GND (power), 40 I/O0 A7 (io), 41 I/O1 A6 (io), 42 I/O2 A5 (io), 43 I/O3 A4 (io), 44 I/O4 A3 (io)

## M4-32/32-15VC48
designator U?
High-Performance EE CMOS In-System Programmable Logic
footprint TQFP48_N (Thin QFP, 48-Leads, Body 7x7mm, Pitch 0.5mm, IPC Medium Density)
footprint TQFP48_L (Thin QFP, 48-Leads, Body 7x7mm, Pitch 0.5mm, IPC High Density)
footprint TQFP48_M (Thin QFP, 48-Leads, Body 7x7mm, Pitch 0.5mm, IPC Low Density)
3D model M4-TQFP48 (48-Pin Thin Quad Flat Pack 0.5 mm Pitch)
pins: 1 I/O5 A2 (io), 2 I/O6 A1 (io), 3 I/O7 A0 (io), 4 TDI (in), 5 CLK0/IN0 (in), 6 NC, 7 GND (power), 8 TCK (in), 9 I/O8 A8 (io), 10 I/O9 A9 (io), 11 I/O10 A10 (io), 12 I/O11 A11 (io), 13 I/O12 A12 (io), 14 I/O13 A13 (io), 15 I/O14 A14 (io), 16 I/O15 A15 (io), 17 VCC (power), 18 NC, 19 GND (power), 20 I/O16 B15 (io), 21 I/O17 B14 (io), 22 I/O18 B13 (io), 23 I/O19 B12 (io), 24 I/O20 B11 (io), 25 I/O21 B10 (io), 26 I/O22 B9 (io), 27 I/O23 B8 (io), 28 TMS (in), 29 CLK1/IN1 (in), 30 NC, 31 GND (power), 32 TDO (out), 33 I/O24 B0 (io), 34 I/O25 B1 (io), 35 I/O26 B2 (io), 36 I/O27 B3 (io), 37 I/O28 B4 (io), 38 I/O29 B5 (io), 39 I/O30 B6 (io), 40 I/O31 B7 (io), 41 VCC (power), 42 NC, 43 GND (power), 44 I/O0 A7 (io), 45 I/O1 A6 (io), 46 I/O2 A5 (io), 47 I/O3 A4 (io), 48 I/O4 A3 (io)

## M4-32/32-18JI
designator U?
High-Performance EE CMOS In-System Programmable Logic
footprint PLCC44_N (Leaded Chip Carrier, 44-Leads, Body 16.6x16.6mm, Pitch 1.27mm, IPC Medium Density)
footprint PLCC44_L (Leaded Chip Carrier, 44-Leads, Body 16.6x16.6mm, Pitch 1.27mm, IPC High Density)
footprint PLCC44_M (Leaded Chip Carrier, 44-Leads, Body 16.6x16.6mm, Pitch 1.27mm, IPC Low Density)
3D model M4-PLCC44 (44-Pin Leaded Chip Carrier 1.27 mm Pitch)
pins: 1 GND (power), 2 I/O0 A7 (io), 3 I/O1 A6 (io), 4 I/O2 A5 (io), 5 I/O3 A4 (io), 6 I/O4 A3 (io), 7 I/O5 A2 (io), 8 I/O6 A1 (io), 9 I/O7 A0 (io), 10 TDI (in), 11 CLK0/IN0 (in), 12 GND (power), 13 TCK (in), 14 I/O8 A8 (io), 15 I/O9 A9 (io), 16 I/O10 A10 (io), 17 I/O11 A11 (io), 18 I/O12 A12 (io), 19 I/O13 A13 (io), 20 I/O14 A14 (io), 21 I/O15 A15 (io), 22 VCC (power), 23 GND (power), 24 I/O16 B15 (io), 25 I/O17 B14 (io), 26 I/O18 B13 (io), 27 I/O19 B12 (io), 28 I/O20 B11 (io), 29 I/O21 B10 (io), 30 I/O22 B9 (io), 31 I/O23 B8 (io), 32 TMS (in), 33 CLK1/IN1 (in), 34 GND (power), 35 TDO (out), 36 I/O24 B0 (io), 37 I/O25 B1 (io), 38 I/O26 B2 (io), 39 I/O27 B3 (io), 40 I/O28 B4 (io), 41 I/O29 B5 (io), 42 I/O30 B6 (io), 43 I/O31 B7 (io), 44 VCC (power)

## M4-32/32-18VI
designator U?
High-Performance EE CMOS In-System Programmable Logic
footprint TQFP44_N (Thin QFP, 44-Leads, Body 10x10mm, Pitch 0.8mm, IPC Medium Density)
footprint TQFP44_L (Thin QFP, 44-Leads, Body 10x10mm, Pitch 0.8mm, IPC High Density)
footprint TQFP44_M (Thin QFP, 44-Leads, Body 10x10mm, Pitch 0.8mm, IPC Low Density)
3D model M4-TQFP44 (44-Pin Thin Quad Flat Pack 0.8 mm Pitch)
pins: 1 I/O5 A2 (io), 2 I/O6 A1 (io), 3 I/O7 A0 (io), 4 TDI (in), 5 CLK0/IN0 (in), 6 GND (power), 7 TCK (in), 8 I/O8 A8 (io), 9 I/O9 A9 (io), 10 I/O10 A10 (io), 11 I/O11 A11 (io), 12 I/O12 A12 (io), 13 I/O13 A13 (io), 14 I/O14 A14 (io), 15 I/O15 A15 (io), 16 VCC (power), 17 GND (power), 18 I/O16 B15 (io), 19 I/O17 B14 (io), 20 I/O18 B13 (io), 21 I/O19 B12 (io), 22 I/O20 B11 (io), 23 I/O21 B10 (io), 24 I/O22 B9 (io), 25 I/O23 B8 (io), 26 TMS (in), 27 CLK1/IN1 (in), 28 GND (power), 29 TDO (out), 30 I/O24 B0 (io), 31 I/O25 B1 (io), 32 I/O26 B2 (io), 33 I/O27 B3 (io), 34 I/O28 B4 (io), 35 I/O29 B5 (io), 36 I/O30 B6 (io), 37 I/O31 B7 (io), 38 VCC (power), 39 GND (power), 40 I/O0 A7 (io), 41 I/O1 A6 (io), 42 I/O2 A5 (io), 43 I/O3 A4 (io), 44 I/O4 A3 (io)

## M4-32/32-18VI48
designator U?
High-Performance EE CMOS In-System Programmable Logic
footprint TQFP48_N (Thin QFP, 48-Leads, Body 7x7mm, Pitch 0.5mm, IPC Medium Density)
footprint TQFP48_L (Thin QFP, 48-Leads, Body 7x7mm, Pitch 0.5mm, IPC High Density)
footprint TQFP48_M (Thin QFP, 48-Leads, Body 7x7mm, Pitch 0.5mm, IPC Low Density)
3D model M4-TQFP48 (48-Pin Thin Quad Flat Pack 0.5 mm Pitch)
pins: 1 I/O5 A2 (io), 2 I/O6 A1 (io), 3 I/O7 A0 (io), 4 TDI (in), 5 CLK0/IN0 (in), 6 NC, 7 GND (power), 8 TCK (in), 9 I/O8 A8 (io), 10 I/O9 A9 (io), 11 I/O10 A10 (io), 12 I/O11 A11 (io), 13 I/O12 A12 (io), 14 I/O13 A13 (io), 15 I/O14 A14 (io), 16 I/O15 A15 (io), 17 VCC (power), 18 NC, 19 GND (power), 20 I/O16 B15 (io), 21 I/O17 B14 (io), 22 I/O18 B13 (io), 23 I/O19 B12 (io), 24 I/O20 B11 (io), 25 I/O21 B10 (io), 26 I/O22 B9 (io), 27 I/O23 B8 (io), 28 TMS (in), 29 CLK1/IN1 (in), 30 NC, 31 GND (power), 32 TDO (out), 33 I/O24 B0 (io), 34 I/O25 B1 (io), 35 I/O26 B2 (io), 36 I/O27 B3 (io), 37 I/O28 B4 (io), 38 I/O29 B5 (io), 39 I/O30 B6 (io), 40 I/O31 B7 (io), 41 VCC (power), 42 NC, 43 GND (power), 44 I/O0 A7 (io), 45 I/O1 A6 (io), 46 I/O2 A5 (io), 47 I/O3 A4 (io), 48 I/O4 A3 (io)

## M4-64/32-7JC
designator U?
High-Performance EE CMOS In-System Programmable Logic
footprint PLCC44_N (Leaded Chip Carrier, 44-Leads, Body 16.6x16.6mm, Pitch 1.27mm, IPC Medium Density)
footprint PLCC44_L (Leaded Chip Carrier, 44-Leads, Body 16.6x16.6mm, Pitch 1.27mm, IPC High Density)
footprint PLCC44_M (Leaded Chip Carrier, 44-Leads, Body 16.6x16.6mm, Pitch 1.27mm, IPC Low Density)
3D model M4-PLCC44 (44-Pin Leaded Chip Carrier 1.27 mm Pitch)
pins: 1 GND (power), 2 I/O0 A7 (io), 3 I/O1 A6 (io), 4 I/O2 A5 (io), 5 I/O3 A4 (io), 6 I/O4 A3 (io), 7 I/O5 A2 (io), 8 I/O6 A1 (io), 9 I/O7 A0 (io), 10 TDI (in), 11 CLK0/IN0 (in), 12 GND (power), 13 TCK (in), 14 I/O8 B0 (io), 15 I/O9 B1 (io), 16 I/O10 B2 (io), 17 I/O11 B3 (io), 18 I/O12 B4 (io), 19 I/O13 B5 (io), 20 I/O14 B6 (io), 21 I/O15 B7 (io), 22 VCC (power), 23 GND (power), 24 I/O16 C7 (io), 25 I/O17 C6 (io), 26 I/O18 C5 (io), 27 I/O19 C4 (io), 28 I/O20 C3 (io), 29 I/O21 C2 (io), 30 I/O22 C1 (io), 31 I/O23 C0 (io), 32 TMS (in), 33 CLK1/IN1 (in), 34 GND (power), 35 TDO (out), 36 I/O24 D0 (io), 37 I/O25 D1 (io), 38 I/O26 D2 (io), 39 I/O27 D3 (io), 40 I/O28 D4 (io), 41 I/O29 D5 (io), 42 I/O30 D6 (io), 43 I/O31 D7 (io), 44 VCC (power)

## M4-64/32-7VC
designator U?
High-Performance EE CMOS In-System Programmable Logic
footprint TQFP44_N (Thin QFP, 44-Leads, Body 10x10mm, Pitch 0.8mm, IPC Medium Density)
footprint TQFP44_L (Thin QFP, 44-Leads, Body 10x10mm, Pitch 0.8mm, IPC High Density)
footprint TQFP44_M (Thin QFP, 44-Leads, Body 10x10mm, Pitch 0.8mm, IPC Low Density)
3D model M4-TQFP44 (44-Pin Thin Quad Flat Pack 0.8 mm Pitch)
pins: 1 I/O5 A2 (io), 2 I/O6 A1 (io), 3 I/O7 A0 (io), 4 TDI (in), 5 CLK0/IN0 (in), 6 GND (power), 7 TCK (in), 8 I/O8 B0 (io), 9 I/O9 B1 (io), 10 I/O10 B2 (io), 11 I/O11 B3 (io), 12 I/O12 B4 (io), 13 I/O13 B5 (io), 14 I/O14 B6 (io), 15 I/O15 B7 (io), 16 VCC (power), 17 GND (power), 18 I/O16 C7 (io), 19 I/O17 C6 (io), 20 I/O18 C5 (io), 21 I/O19 C4 (io), 22 I/O20 C3 (io), 23 I/O21 C2 (io), 24 I/O22 C1 (io), 25 I/O23 C0 (io), 26 TMS (in), 27 CLK1/IN1 (in), 28 GND (power), 29 TDO (out), 30 I/O24 D0 (io), 31 I/O25 D1 (io), 32 I/O26 D2 (io), 33 I/O27 D3 (io), 34 I/O28 D4 (io), 35 I/O29 D5 (io), 36 I/O30 D6 (io), 37 I/O31 D7 (io), 38 VCC (power), 39 GND (power), 40 I/O0 A7 (io), 41 I/O1 A6 (io), 42 I/O2 A5 (io), 43 I/O3 A4 (io), 44 I/O4 A3 (io)

## M4-64/32-7VC48
designator U?
High-Performance EE CMOS In-System Programmable Logic
footprint TQFP48_N (Thin QFP, 48-Leads, Body 7x7mm, Pitch 0.5mm, IPC Medium Density)
footprint TQFP48_L (Thin QFP, 48-Leads, Body 7x7mm, Pitch 0.5mm, IPC High Density)
footprint TQFP48_M (Thin QFP, 48-Leads, Body 7x7mm, Pitch 0.5mm, IPC Low Density)
3D model M4-TQFP48 (48-Pin Thin Quad Flat Pack 0.5 mm Pitch)
pins: 1 I/O5 A2 (io), 2 I/O6 A1 (io), 3 I/O7 A0 (io), 4 TDI (in), 5 CLK0/IN0 (in), 6 NC, 7 GND (power), 8 TCK (in), 9 I/O8 B0 (io), 10 I/O9 B1 (io), 11 I/O10 B2 (io), 12 I/O11 B3 (io), 13 I/O12 B4 (io), 14 I/O13 B5 (io), 15 I/O14 B6 (io), 16 I/O15 B7 (io), 17 VCC (power), 18 NC, 19 GND (power), 20 I/O16 C7 (io), 21 I/O17 C6 (io), 22 I/O18 C5 (io), 23 I/O19 C4 (io), 24 I/O20 C3 (io), 25 I/O21 C2 (io), 26 I/O22 C1 (io), 27 I/O23 C0 (io), 28 TMS (in), 29 CLK1/IN1 (in), 30 NC, 31 GND (power), 32 TDO (out), 33 I/O24 D0 (io), 34 I/O25 D1 (io), 35 I/O26 D2 (io), 36 I/O27 D3 (io), 37 I/O28 D4 (io), 38 I/O29 D5 (io), 39 I/O30 D6 (io), 40 I/O31 D7 (io), 41 VCC (power), 42 NC, 43 GND (power), 44 I/O0 A7 (io), 45 I/O1 A6 (io), 46 I/O2 A5 (io), 47 I/O3 A4 (io), 48 I/O4 A3 (io)

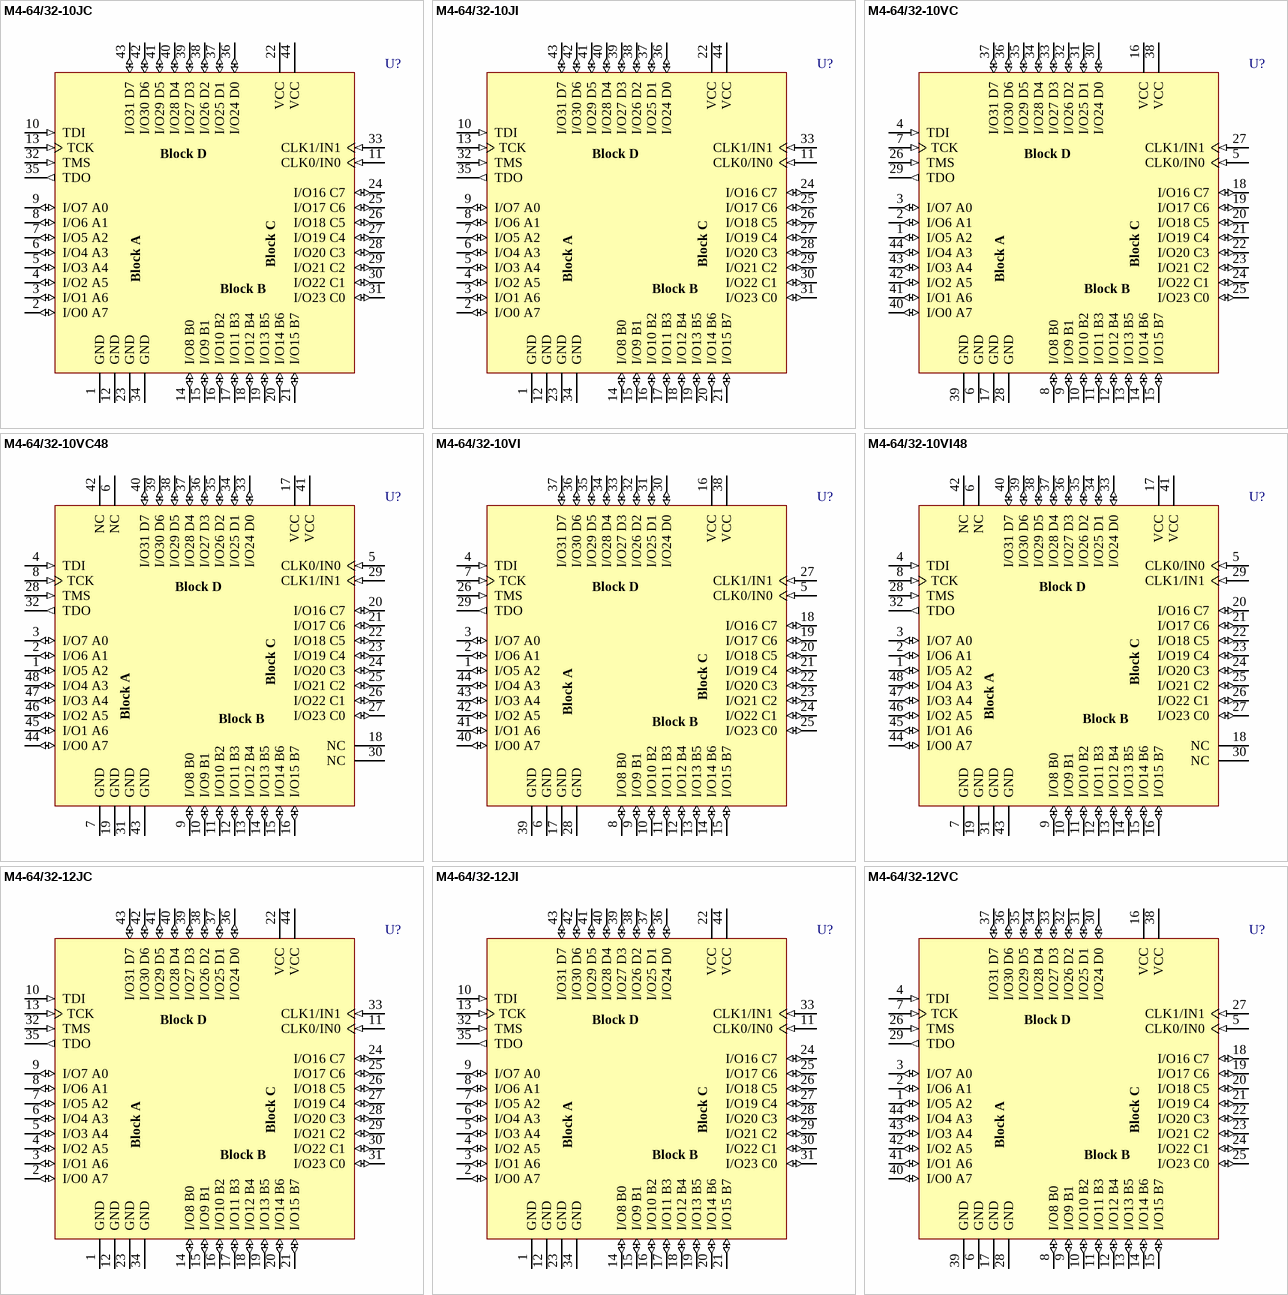
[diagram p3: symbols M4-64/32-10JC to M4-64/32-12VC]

## M4-64/32-10JC
designator U?
High-Performance EE CMOS In-System Programmable Logic
footprint PLCC44_N (Leaded Chip Carrier, 44-Leads, Body 16.6x16.6mm, Pitch 1.27mm, IPC Medium Density)
footprint PLCC44_L (Leaded Chip Carrier, 44-Leads, Body 16.6x16.6mm, Pitch 1.27mm, IPC High Density)
footprint PLCC44_M (Leaded Chip Carrier, 44-Leads, Body 16.6x16.6mm, Pitch 1.27mm, IPC Low Density)
3D model M4-PLCC44 (44-Pin Leaded Chip Carrier 1.27 mm Pitch)
pins: 1 GND (power), 2 I/O0 A7 (io), 3 I/O1 A6 (io), 4 I/O2 A5 (io), 5 I/O3 A4 (io), 6 I/O4 A3 (io), 7 I/O5 A2 (io), 8 I/O6 A1 (io), 9 I/O7 A0 (io), 10 TDI (in), 11 CLK0/IN0 (in), 12 GND (power), 13 TCK (in), 14 I/O8 B0 (io), 15 I/O9 B1 (io), 16 I/O10 B2 (io), 17 I/O11 B3 (io), 18 I/O12 B4 (io), 19 I/O13 B5 (io), 20 I/O14 B6 (io), 21 I/O15 B7 (io), 22 VCC (power), 23 GND (power), 24 I/O16 C7 (io), 25 I/O17 C6 (io), 26 I/O18 C5 (io), 27 I/O19 C4 (io), 28 I/O20 C3 (io), 29 I/O21 C2 (io), 30 I/O22 C1 (io), 31 I/O23 C0 (io), 32 TMS (in), 33 CLK1/IN1 (in), 34 GND (power), 35 TDO (out), 36 I/O24 D0 (io), 37 I/O25 D1 (io), 38 I/O26 D2 (io), 39 I/O27 D3 (io), 40 I/O28 D4 (io), 41 I/O29 D5 (io), 42 I/O30 D6 (io), 43 I/O31 D7 (io), 44 VCC (power)

## M4-64/32-10JI
designator U?
High-Performance EE CMOS In-System Programmable Logic
footprint PLCC44_N (Leaded Chip Carrier, 44-Leads, Body 16.6x16.6mm, Pitch 1.27mm, IPC Medium Density)
footprint PLCC44_L (Leaded Chip Carrier, 44-Leads, Body 16.6x16.6mm, Pitch 1.27mm, IPC High Density)
footprint PLCC44_M (Leaded Chip Carrier, 44-Leads, Body 16.6x16.6mm, Pitch 1.27mm, IPC Low Density)
3D model M4-PLCC44 (44-Pin Leaded Chip Carrier 1.27 mm Pitch)
pins: 1 GND (power), 2 I/O0 A7 (io), 3 I/O1 A6 (io), 4 I/O2 A5 (io), 5 I/O3 A4 (io), 6 I/O4 A3 (io), 7 I/O5 A2 (io), 8 I/O6 A1 (io), 9 I/O7 A0 (io), 10 TDI (in), 11 CLK0/IN0 (in), 12 GND (power), 13 TCK (in), 14 I/O8 B0 (io), 15 I/O9 B1 (io), 16 I/O10 B2 (io), 17 I/O11 B3 (io), 18 I/O12 B4 (io), 19 I/O13 B5 (io), 20 I/O14 B6 (io), 21 I/O15 B7 (io), 22 VCC (power), 23 GND (power), 24 I/O16 C7 (io), 25 I/O17 C6 (io), 26 I/O18 C5 (io), 27 I/O19 C4 (io), 28 I/O20 C3 (io), 29 I/O21 C2 (io), 30 I/O22 C1 (io), 31 I/O23 C0 (io), 32 TMS (in), 33 CLK1/IN1 (in), 34 GND (power), 35 TDO (out), 36 I/O24 D0 (io), 37 I/O25 D1 (io), 38 I/O26 D2 (io), 39 I/O27 D3 (io), 40 I/O28 D4 (io), 41 I/O29 D5 (io), 42 I/O30 D6 (io), 43 I/O31 D7 (io), 44 VCC (power)

## M4-64/32-10VC
designator U?
High-Performance EE CMOS In-System Programmable Logic
footprint TQFP44_N (Thin QFP, 44-Leads, Body 10x10mm, Pitch 0.8mm, IPC Medium Density)
footprint TQFP44_L (Thin QFP, 44-Leads, Body 10x10mm, Pitch 0.8mm, IPC High Density)
footprint TQFP44_M (Thin QFP, 44-Leads, Body 10x10mm, Pitch 0.8mm, IPC Low Density)
3D model M4-TQFP44 (44-Pin Thin Quad Flat Pack 0.8 mm Pitch)
pins: 1 I/O5 A2 (io), 2 I/O6 A1 (io), 3 I/O7 A0 (io), 4 TDI (in), 5 CLK0/IN0 (in), 6 GND (power), 7 TCK (in), 8 I/O8 B0 (io), 9 I/O9 B1 (io), 10 I/O10 B2 (io), 11 I/O11 B3 (io), 12 I/O12 B4 (io), 13 I/O13 B5 (io), 14 I/O14 B6 (io), 15 I/O15 B7 (io), 16 VCC (power), 17 GND (power), 18 I/O16 C7 (io), 19 I/O17 C6 (io), 20 I/O18 C5 (io), 21 I/O19 C4 (io), 22 I/O20 C3 (io), 23 I/O21 C2 (io), 24 I/O22 C1 (io), 25 I/O23 C0 (io), 26 TMS (in), 27 CLK1/IN1 (in), 28 GND (power), 29 TDO (out), 30 I/O24 D0 (io), 31 I/O25 D1 (io), 32 I/O26 D2 (io), 33 I/O27 D3 (io), 34 I/O28 D4 (io), 35 I/O29 D5 (io), 36 I/O30 D6 (io), 37 I/O31 D7 (io), 38 VCC (power), 39 GND (power), 40 I/O0 A7 (io), 41 I/O1 A6 (io), 42 I/O2 A5 (io), 43 I/O3 A4 (io), 44 I/O4 A3 (io)

## M4-64/32-10VC48
designator U?
High-Performance EE CMOS In-System Programmable Logic
footprint TQFP48_N (Thin QFP, 48-Leads, Body 7x7mm, Pitch 0.5mm, IPC Medium Density)
footprint TQFP48_L (Thin QFP, 48-Leads, Body 7x7mm, Pitch 0.5mm, IPC High Density)
footprint TQFP48_M (Thin QFP, 48-Leads, Body 7x7mm, Pitch 0.5mm, IPC Low Density)
3D model M4-TQFP48 (48-Pin Thin Quad Flat Pack 0.5 mm Pitch)
pins: 1 I/O5 A2 (io), 2 I/O6 A1 (io), 3 I/O7 A0 (io), 4 TDI (in), 5 CLK0/IN0 (in), 6 NC, 7 GND (power), 8 TCK (in), 9 I/O8 B0 (io), 10 I/O9 B1 (io), 11 I/O10 B2 (io), 12 I/O11 B3 (io), 13 I/O12 B4 (io), 14 I/O13 B5 (io), 15 I/O14 B6 (io), 16 I/O15 B7 (io), 17 VCC (power), 18 NC, 19 GND (power), 20 I/O16 C7 (io), 21 I/O17 C6 (io), 22 I/O18 C5 (io), 23 I/O19 C4 (io), 24 I/O20 C3 (io), 25 I/O21 C2 (io), 26 I/O22 C1 (io), 27 I/O23 C0 (io), 28 TMS (in), 29 CLK1/IN1 (in), 30 NC, 31 GND (power), 32 TDO (out), 33 I/O24 D0 (io), 34 I/O25 D1 (io), 35 I/O26 D2 (io), 36 I/O27 D3 (io), 37 I/O28 D4 (io), 38 I/O29 D5 (io), 39 I/O30 D6 (io), 40 I/O31 D7 (io), 41 VCC (power), 42 NC, 43 GND (power), 44 I/O0 A7 (io), 45 I/O1 A6 (io), 46 I/O2 A5 (io), 47 I/O3 A4 (io), 48 I/O4 A3 (io)

## M4-64/32-10VI
designator U?
High-Performance EE CMOS In-System Programmable Logic
footprint TQFP44_N (Thin QFP, 44-Leads, Body 10x10mm, Pitch 0.8mm, IPC Medium Density)
footprint TQFP44_L (Thin QFP, 44-Leads, Body 10x10mm, Pitch 0.8mm, IPC High Density)
footprint TQFP44_M (Thin QFP, 44-Leads, Body 10x10mm, Pitch 0.8mm, IPC Low Density)
3D model M4-TQFP44 (44-Pin Thin Quad Flat Pack 0.8 mm Pitch)
pins: 1 I/O5 A2 (io), 2 I/O6 A1 (io), 3 I/O7 A0 (io), 4 TDI (in), 5 CLK0/IN0 (in), 6 GND (power), 7 TCK (in), 8 I/O8 B0 (io), 9 I/O9 B1 (io), 10 I/O10 B2 (io), 11 I/O11 B3 (io), 12 I/O12 B4 (io), 13 I/O13 B5 (io), 14 I/O14 B6 (io), 15 I/O15 B7 (io), 16 VCC (power), 17 GND (power), 18 I/O16 C7 (io), 19 I/O17 C6 (io), 20 I/O18 C5 (io), 21 I/O19 C4 (io), 22 I/O20 C3 (io), 23 I/O21 C2 (io), 24 I/O22 C1 (io), 25 I/O23 C0 (io), 26 TMS (in), 27 CLK1/IN1 (in), 28 GND (power), 29 TDO (out), 30 I/O24 D0 (io), 31 I/O25 D1 (io), 32 I/O26 D2 (io), 33 I/O27 D3 (io), 34 I/O28 D4 (io), 35 I/O29 D5 (io), 36 I/O30 D6 (io), 37 I/O31 D7 (io), 38 VCC (power), 39 GND (power), 40 I/O0 A7 (io), 41 I/O1 A6 (io), 42 I/O2 A5 (io), 43 I/O3 A4 (io), 44 I/O4 A3 (io)

## M4-64/32-10VI48
designator U?
High-Performance EE CMOS In-System Programmable Logic
footprint TQFP48_N (Thin QFP, 48-Leads, Body 7x7mm, Pitch 0.5mm, IPC Medium Density)
footprint TQFP48_L (Thin QFP, 48-Leads, Body 7x7mm, Pitch 0.5mm, IPC High Density)
footprint TQFP48_M (Thin QFP, 48-Leads, Body 7x7mm, Pitch 0.5mm, IPC Low Density)
3D model M4-TQFP48 (48-Pin Thin Quad Flat Pack 0.5 mm Pitch)
pins: 1 I/O5 A2 (io), 2 I/O6 A1 (io), 3 I/O7 A0 (io), 4 TDI (in), 5 CLK0/IN0 (in), 6 NC, 7 GND (power), 8 TCK (in), 9 I/O8 B0 (io), 10 I/O9 B1 (io), 11 I/O10 B2 (io), 12 I/O11 B3 (io), 13 I/O12 B4 (io), 14 I/O13 B5 (io), 15 I/O14 B6 (io), 16 I/O15 B7 (io), 17 VCC (power), 18 NC, 19 GND (power), 20 I/O16 C7 (io), 21 I/O17 C6 (io), 22 I/O18 C5 (io), 23 I/O19 C4 (io), 24 I/O20 C3 (io), 25 I/O21 C2 (io), 26 I/O22 C1 (io), 27 I/O23 C0 (io), 28 TMS (in), 29 CLK1/IN1 (in), 30 NC, 31 GND (power), 32 TDO (out), 33 I/O24 D0 (io), 34 I/O25 D1 (io), 35 I/O26 D2 (io), 36 I/O27 D3 (io), 37 I/O28 D4 (io), 38 I/O29 D5 (io), 39 I/O30 D6 (io), 40 I/O31 D7 (io), 41 VCC (power), 42 NC, 43 GND (power), 44 I/O0 A7 (io), 45 I/O1 A6 (io), 46 I/O2 A5 (io), 47 I/O3 A4 (io), 48 I/O4 A3 (io)

## M4-64/32-12JC
designator U?
High-Performance EE CMOS In-System Programmable Logic
footprint PLCC44_N (Leaded Chip Carrier, 44-Leads, Body 16.6x16.6mm, Pitch 1.27mm, IPC Medium Density)
footprint PLCC44_L (Leaded Chip Carrier, 44-Leads, Body 16.6x16.6mm, Pitch 1.27mm, IPC High Density)
footprint PLCC44_M (Leaded Chip Carrier, 44-Leads, Body 16.6x16.6mm, Pitch 1.27mm, IPC Low Density)
3D model M4-PLCC44 (44-Pin Leaded Chip Carrier 1.27 mm Pitch)
pins: 1 GND (power), 2 I/O0 A7 (io), 3 I/O1 A6 (io), 4 I/O2 A5 (io), 5 I/O3 A4 (io), 6 I/O4 A3 (io), 7 I/O5 A2 (io), 8 I/O6 A1 (io), 9 I/O7 A0 (io), 10 TDI (in), 11 CLK0/IN0 (in), 12 GND (power), 13 TCK (in), 14 I/O8 B0 (io), 15 I/O9 B1 (io), 16 I/O10 B2 (io), 17 I/O11 B3 (io), 18 I/O12 B4 (io), 19 I/O13 B5 (io), 20 I/O14 B6 (io), 21 I/O15 B7 (io), 22 VCC (power), 23 GND (power), 24 I/O16 C7 (io), 25 I/O17 C6 (io), 26 I/O18 C5 (io), 27 I/O19 C4 (io), 28 I/O20 C3 (io), 29 I/O21 C2 (io), 30 I/O22 C1 (io), 31 I/O23 C0 (io), 32 TMS (in), 33 CLK1/IN1 (in), 34 GND (power), 35 TDO (out), 36 I/O24 D0 (io), 37 I/O25 D1 (io), 38 I/O26 D2 (io), 39 I/O27 D3 (io), 40 I/O28 D4 (io), 41 I/O29 D5 (io), 42 I/O30 D6 (io), 43 I/O31 D7 (io), 44 VCC (power)

## M4-64/32-12JI
designator U?
High-Performance EE CMOS In-System Programmable Logic
footprint PLCC44_N (Leaded Chip Carrier, 44-Leads, Body 16.6x16.6mm, Pitch 1.27mm, IPC Medium Density)
footprint PLCC44_L (Leaded Chip Carrier, 44-Leads, Body 16.6x16.6mm, Pitch 1.27mm, IPC High Density)
footprint PLCC44_M (Leaded Chip Carrier, 44-Leads, Body 16.6x16.6mm, Pitch 1.27mm, IPC Low Density)
3D model M4-PLCC44 (44-Pin Leaded Chip Carrier 1.27 mm Pitch)
pins: 1 GND (power), 2 I/O0 A7 (io), 3 I/O1 A6 (io), 4 I/O2 A5 (io), 5 I/O3 A4 (io), 6 I/O4 A3 (io), 7 I/O5 A2 (io), 8 I/O6 A1 (io), 9 I/O7 A0 (io), 10 TDI (in), 11 CLK0/IN0 (in), 12 GND (power), 13 TCK (in), 14 I/O8 B0 (io), 15 I/O9 B1 (io), 16 I/O10 B2 (io), 17 I/O11 B3 (io), 18 I/O12 B4 (io), 19 I/O13 B5 (io), 20 I/O14 B6 (io), 21 I/O15 B7 (io), 22 VCC (power), 23 GND (power), 24 I/O16 C7 (io), 25 I/O17 C6 (io), 26 I/O18 C5 (io), 27 I/O19 C4 (io), 28 I/O20 C3 (io), 29 I/O21 C2 (io), 30 I/O22 C1 (io), 31 I/O23 C0 (io), 32 TMS (in), 33 CLK1/IN1 (in), 34 GND (power), 35 TDO (out), 36 I/O24 D0 (io), 37 I/O25 D1 (io), 38 I/O26 D2 (io), 39 I/O27 D3 (io), 40 I/O28 D4 (io), 41 I/O29 D5 (io), 42 I/O30 D6 (io), 43 I/O31 D7 (io), 44 VCC (power)

## M4-64/32-12VC
designator U?
High-Performance EE CMOS In-System Programmable Logic
footprint TQFP44_N (Thin QFP, 44-Leads, Body 10x10mm, Pitch 0.8mm, IPC Medium Density)
footprint TQFP44_L (Thin QFP, 44-Leads, Body 10x10mm, Pitch 0.8mm, IPC High Density)
footprint TQFP44_M (Thin QFP, 44-Leads, Body 10x10mm, Pitch 0.8mm, IPC Low Density)
3D model M4-TQFP44 (44-Pin Thin Quad Flat Pack 0.8 mm Pitch)
pins: 1 I/O5 A2 (io), 2 I/O6 A1 (io), 3 I/O7 A0 (io), 4 TDI (in), 5 CLK0/IN0 (in), 6 GND (power), 7 TCK (in), 8 I/O8 B0 (io), 9 I/O9 B1 (io), 10 I/O10 B2 (io), 11 I/O11 B3 (io), 12 I/O12 B4 (io), 13 I/O13 B5 (io), 14 I/O14 B6 (io), 15 I/O15 B7 (io), 16 VCC (power), 17 GND (power), 18 I/O16 C7 (io), 19 I/O17 C6 (io), 20 I/O18 C5 (io), 21 I/O19 C4 (io), 22 I/O20 C3 (io), 23 I/O21 C2 (io), 24 I/O22 C1 (io), 25 I/O23 C0 (io), 26 TMS (in), 27 CLK1/IN1 (in), 28 GND (power), 29 TDO (out), 30 I/O24 D0 (io), 31 I/O25 D1 (io), 32 I/O26 D2 (io), 33 I/O27 D3 (io), 34 I/O28 D4 (io), 35 I/O29 D5 (io), 36 I/O30 D6 (io), 37 I/O31 D7 (io), 38 VCC (power), 39 GND (power), 40 I/O0 A7 (io), 41 I/O1 A6 (io), 42 I/O2 A5 (io), 43 I/O3 A4 (io), 44 I/O4 A3 (io)

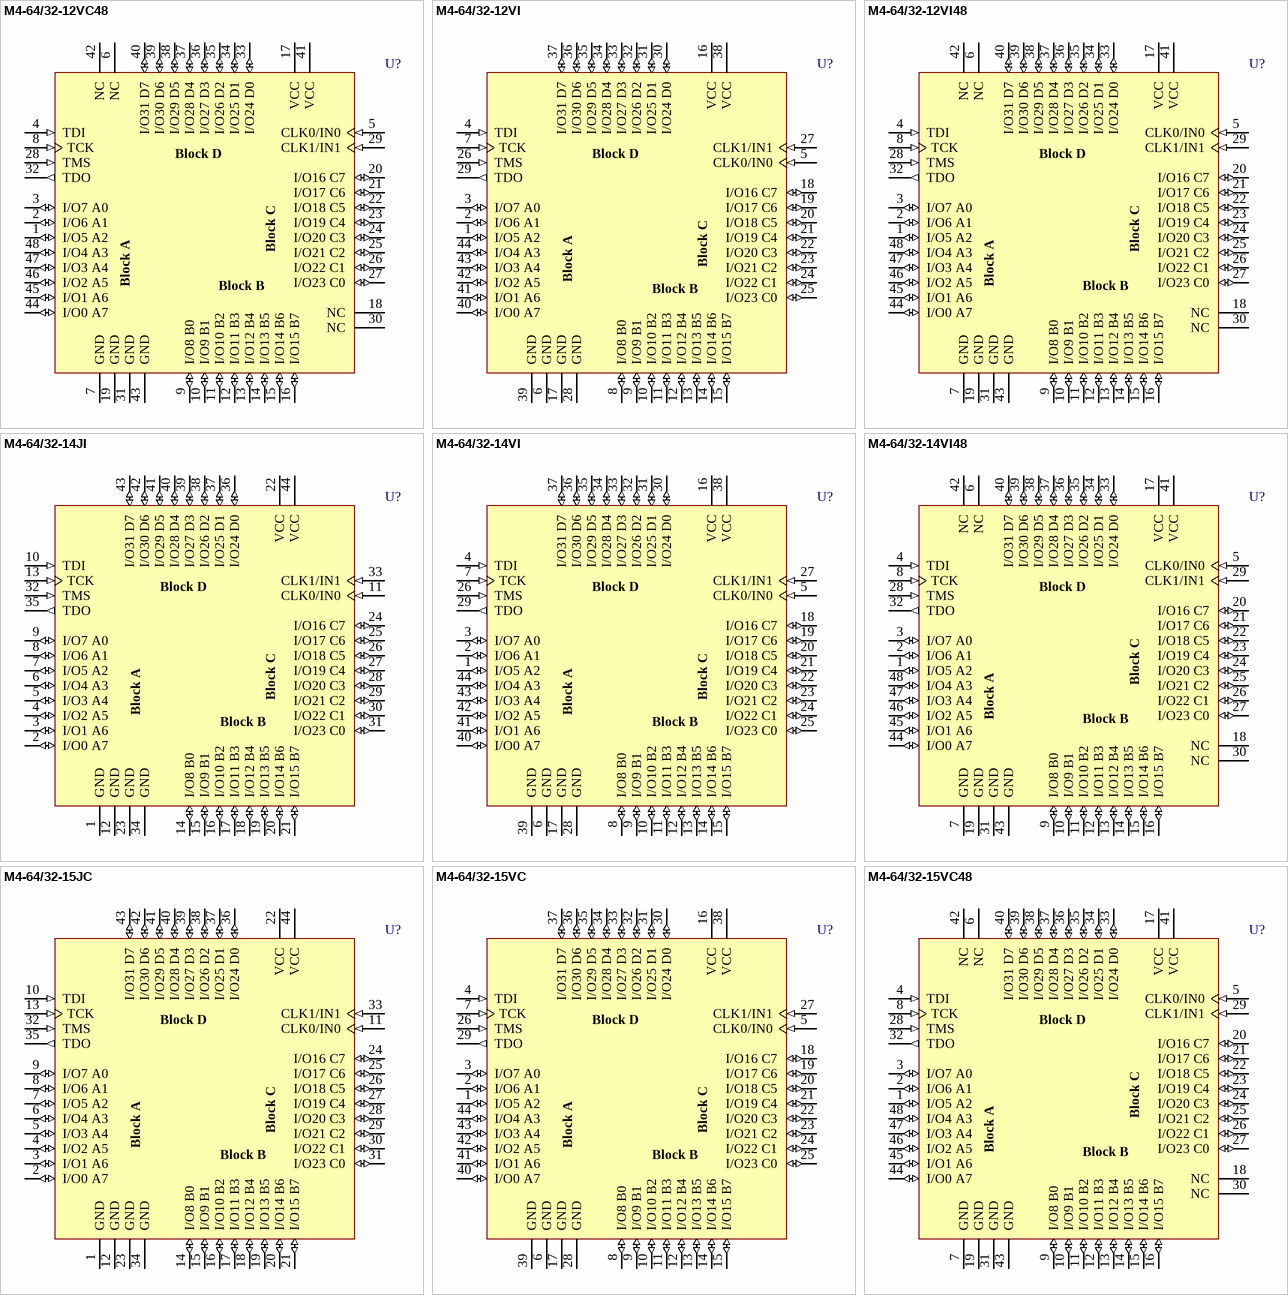
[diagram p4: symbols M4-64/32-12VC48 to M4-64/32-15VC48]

## M4-64/32-12VC48
designator U?
High-Performance EE CMOS In-System Programmable Logic
footprint TQFP48_N (Thin QFP, 48-Leads, Body 7x7mm, Pitch 0.5mm, IPC Medium Density)
footprint TQFP48_L (Thin QFP, 48-Leads, Body 7x7mm, Pitch 0.5mm, IPC High Density)
footprint TQFP48_M (Thin QFP, 48-Leads, Body 7x7mm, Pitch 0.5mm, IPC Low Density)
3D model M4-TQFP48 (48-Pin Thin Quad Flat Pack 0.5 mm Pitch)
pins: 1 I/O5 A2 (io), 2 I/O6 A1 (io), 3 I/O7 A0 (io), 4 TDI (in), 5 CLK0/IN0 (in), 6 NC, 7 GND (power), 8 TCK (in), 9 I/O8 B0 (io), 10 I/O9 B1 (io), 11 I/O10 B2 (io), 12 I/O11 B3 (io), 13 I/O12 B4 (io), 14 I/O13 B5 (io), 15 I/O14 B6 (io), 16 I/O15 B7 (io), 17 VCC (power), 18 NC, 19 GND (power), 20 I/O16 C7 (io), 21 I/O17 C6 (io), 22 I/O18 C5 (io), 23 I/O19 C4 (io), 24 I/O20 C3 (io), 25 I/O21 C2 (io), 26 I/O22 C1 (io), 27 I/O23 C0 (io), 28 TMS (in), 29 CLK1/IN1 (in), 30 NC, 31 GND (power), 32 TDO (out), 33 I/O24 D0 (io), 34 I/O25 D1 (io), 35 I/O26 D2 (io), 36 I/O27 D3 (io), 37 I/O28 D4 (io), 38 I/O29 D5 (io), 39 I/O30 D6 (io), 40 I/O31 D7 (io), 41 VCC (power), 42 NC, 43 GND (power), 44 I/O0 A7 (io), 45 I/O1 A6 (io), 46 I/O2 A5 (io), 47 I/O3 A4 (io), 48 I/O4 A3 (io)

## M4-64/32-12VI
designator U?
High-Performance EE CMOS In-System Programmable Logic
footprint TQFP44_N (Thin QFP, 44-Leads, Body 10x10mm, Pitch 0.8mm, IPC Medium Density)
footprint TQFP44_L (Thin QFP, 44-Leads, Body 10x10mm, Pitch 0.8mm, IPC High Density)
footprint TQFP44_M (Thin QFP, 44-Leads, Body 10x10mm, Pitch 0.8mm, IPC Low Density)
3D model M4-TQFP44 (44-Pin Thin Quad Flat Pack 0.8 mm Pitch)
pins: 1 I/O5 A2 (io), 2 I/O6 A1 (io), 3 I/O7 A0 (io), 4 TDI (in), 5 CLK0/IN0 (in), 6 GND (power), 7 TCK (in), 8 I/O8 B0 (io), 9 I/O9 B1 (io), 10 I/O10 B2 (io), 11 I/O11 B3 (io), 12 I/O12 B4 (io), 13 I/O13 B5 (io), 14 I/O14 B6 (io), 15 I/O15 B7 (io), 16 VCC (power), 17 GND (power), 18 I/O16 C7 (io), 19 I/O17 C6 (io), 20 I/O18 C5 (io), 21 I/O19 C4 (io), 22 I/O20 C3 (io), 23 I/O21 C2 (io), 24 I/O22 C1 (io), 25 I/O23 C0 (io), 26 TMS (in), 27 CLK1/IN1 (in), 28 GND (power), 29 TDO (out), 30 I/O24 D0 (io), 31 I/O25 D1 (io), 32 I/O26 D2 (io), 33 I/O27 D3 (io), 34 I/O28 D4 (io), 35 I/O29 D5 (io), 36 I/O30 D6 (io), 37 I/O31 D7 (io), 38 VCC (power), 39 GND (power), 40 I/O0 A7 (io), 41 I/O1 A6 (io), 42 I/O2 A5 (io), 43 I/O3 A4 (io), 44 I/O4 A3 (io)

## M4-64/32-12VI48
designator U?
High-Performance EE CMOS In-System Programmable Logic
footprint TQFP48_N (Thin QFP, 48-Leads, Body 7x7mm, Pitch 0.5mm, IPC Medium Density)
footprint TQFP48_L (Thin QFP, 48-Leads, Body 7x7mm, Pitch 0.5mm, IPC High Density)
footprint TQFP48_M (Thin QFP, 48-Leads, Body 7x7mm, Pitch 0.5mm, IPC Low Density)
3D model M4-TQFP48 (48-Pin Thin Quad Flat Pack 0.5 mm Pitch)
pins: 1 I/O5 A2 (io), 2 I/O6 A1 (io), 3 I/O7 A0 (io), 4 TDI (in), 5 CLK0/IN0 (in), 6 NC, 7 GND (power), 8 TCK (in), 9 I/O8 B0 (io), 10 I/O9 B1 (io), 11 I/O10 B2 (io), 12 I/O11 B3 (io), 13 I/O12 B4 (io), 14 I/O13 B5 (io), 15 I/O14 B6 (io), 16 I/O15 B7 (io), 17 VCC (power), 18 NC, 19 GND (power), 20 I/O16 C7 (io), 21 I/O17 C6 (io), 22 I/O18 C5 (io), 23 I/O19 C4 (io), 24 I/O20 C3 (io), 25 I/O21 C2 (io), 26 I/O22 C1 (io), 27 I/O23 C0 (io), 28 TMS (in), 29 CLK1/IN1 (in), 30 NC, 31 GND (power), 32 TDO (out), 33 I/O24 D0 (io), 34 I/O25 D1 (io), 35 I/O26 D2 (io), 36 I/O27 D3 (io), 37 I/O28 D4 (io), 38 I/O29 D5 (io), 39 I/O30 D6 (io), 40 I/O31 D7 (io), 41 VCC (power), 42 NC, 43 GND (power), 44 I/O0 A7 (io), 45 I/O1 A6 (io), 46 I/O2 A5 (io), 47 I/O3 A4 (io), 48 I/O4 A3 (io)

## M4-64/32-14JI
designator U?
High-Performance EE CMOS In-System Programmable Logic
footprint PLCC44_N (Leaded Chip Carrier, 44-Leads, Body 16.6x16.6mm, Pitch 1.27mm, IPC Medium Density)
footprint PLCC44_L (Leaded Chip Carrier, 44-Leads, Body 16.6x16.6mm, Pitch 1.27mm, IPC High Density)
footprint PLCC44_M (Leaded Chip Carrier, 44-Leads, Body 16.6x16.6mm, Pitch 1.27mm, IPC Low Density)
3D model M4-PLCC44 (44-Pin Leaded Chip Carrier 1.27 mm Pitch)
pins: 1 GND (power), 2 I/O0 A7 (io), 3 I/O1 A6 (io), 4 I/O2 A5 (io), 5 I/O3 A4 (io), 6 I/O4 A3 (io), 7 I/O5 A2 (io), 8 I/O6 A1 (io), 9 I/O7 A0 (io), 10 TDI (in), 11 CLK0/IN0 (in), 12 GND (power), 13 TCK (in), 14 I/O8 B0 (io), 15 I/O9 B1 (io), 16 I/O10 B2 (io), 17 I/O11 B3 (io), 18 I/O12 B4 (io), 19 I/O13 B5 (io), 20 I/O14 B6 (io), 21 I/O15 B7 (io), 22 VCC (power), 23 GND (power), 24 I/O16 C7 (io), 25 I/O17 C6 (io), 26 I/O18 C5 (io), 27 I/O19 C4 (io), 28 I/O20 C3 (io), 29 I/O21 C2 (io), 30 I/O22 C1 (io), 31 I/O23 C0 (io), 32 TMS (in), 33 CLK1/IN1 (in), 34 GND (power), 35 TDO (out), 36 I/O24 D0 (io), 37 I/O25 D1 (io), 38 I/O26 D2 (io), 39 I/O27 D3 (io), 40 I/O28 D4 (io), 41 I/O29 D5 (io), 42 I/O30 D6 (io), 43 I/O31 D7 (io), 44 VCC (power)

## M4-64/32-14VI
designator U?
High-Performance EE CMOS In-System Programmable Logic
footprint TQFP44_N (Thin QFP, 44-Leads, Body 10x10mm, Pitch 0.8mm, IPC Medium Density)
footprint TQFP44_L (Thin QFP, 44-Leads, Body 10x10mm, Pitch 0.8mm, IPC High Density)
footprint TQFP44_M (Thin QFP, 44-Leads, Body 10x10mm, Pitch 0.8mm, IPC Low Density)
3D model M4-TQFP44 (44-Pin Thin Quad Flat Pack 0.8 mm Pitch)
pins: 1 I/O5 A2 (io), 2 I/O6 A1 (io), 3 I/O7 A0 (io), 4 TDI (in), 5 CLK0/IN0 (in), 6 GND (power), 7 TCK (in), 8 I/O8 B0 (io), 9 I/O9 B1 (io), 10 I/O10 B2 (io), 11 I/O11 B3 (io), 12 I/O12 B4 (io), 13 I/O13 B5 (io), 14 I/O14 B6 (io), 15 I/O15 B7 (io), 16 VCC (power), 17 GND (power), 18 I/O16 C7 (io), 19 I/O17 C6 (io), 20 I/O18 C5 (io), 21 I/O19 C4 (io), 22 I/O20 C3 (io), 23 I/O21 C2 (io), 24 I/O22 C1 (io), 25 I/O23 C0 (io), 26 TMS (in), 27 CLK1/IN1 (in), 28 GND (power), 29 TDO (out), 30 I/O24 D0 (io), 31 I/O25 D1 (io), 32 I/O26 D2 (io), 33 I/O27 D3 (io), 34 I/O28 D4 (io), 35 I/O29 D5 (io), 36 I/O30 D6 (io), 37 I/O31 D7 (io), 38 VCC (power), 39 GND (power), 40 I/O0 A7 (io), 41 I/O1 A6 (io), 42 I/O2 A5 (io), 43 I/O3 A4 (io), 44 I/O4 A3 (io)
